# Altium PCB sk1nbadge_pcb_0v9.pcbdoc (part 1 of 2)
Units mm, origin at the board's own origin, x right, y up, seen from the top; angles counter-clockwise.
Board outline 99 x 74 mm, 4 copper layers (Top Layer, GND Plane, 3V Plane, Bottom Layer); 199 components, 158 nets, 800 pads, 392 vias.
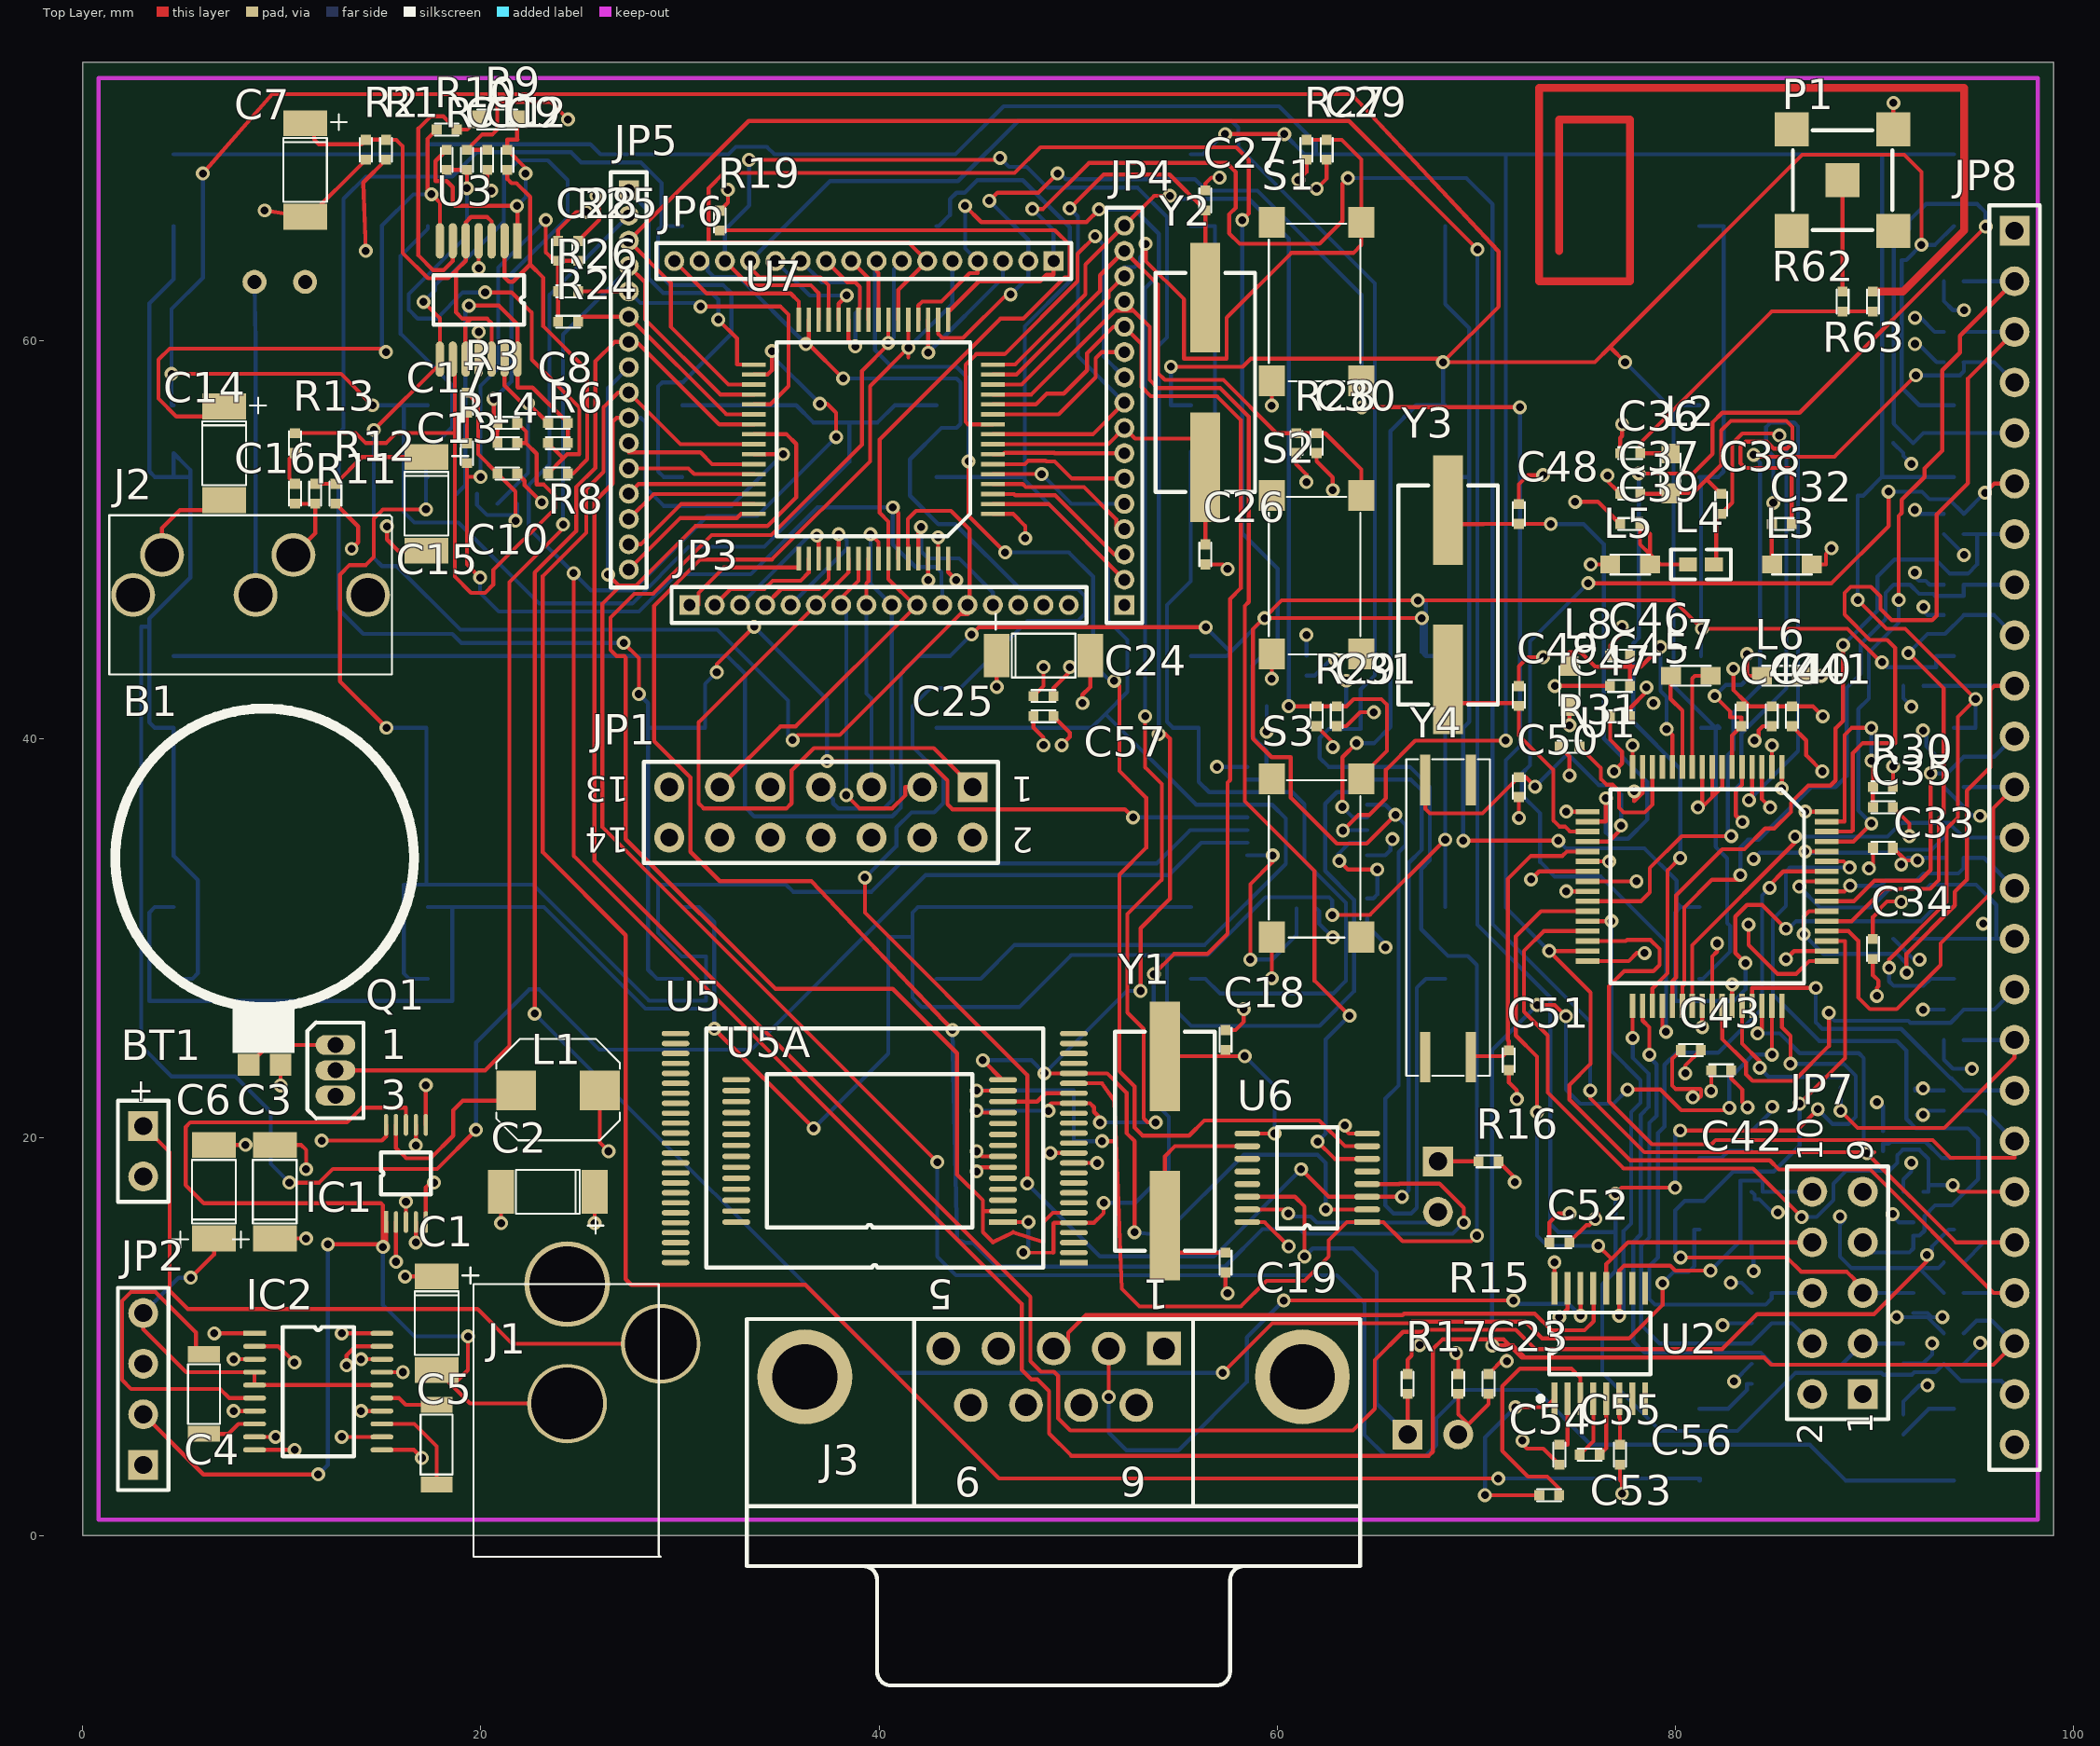
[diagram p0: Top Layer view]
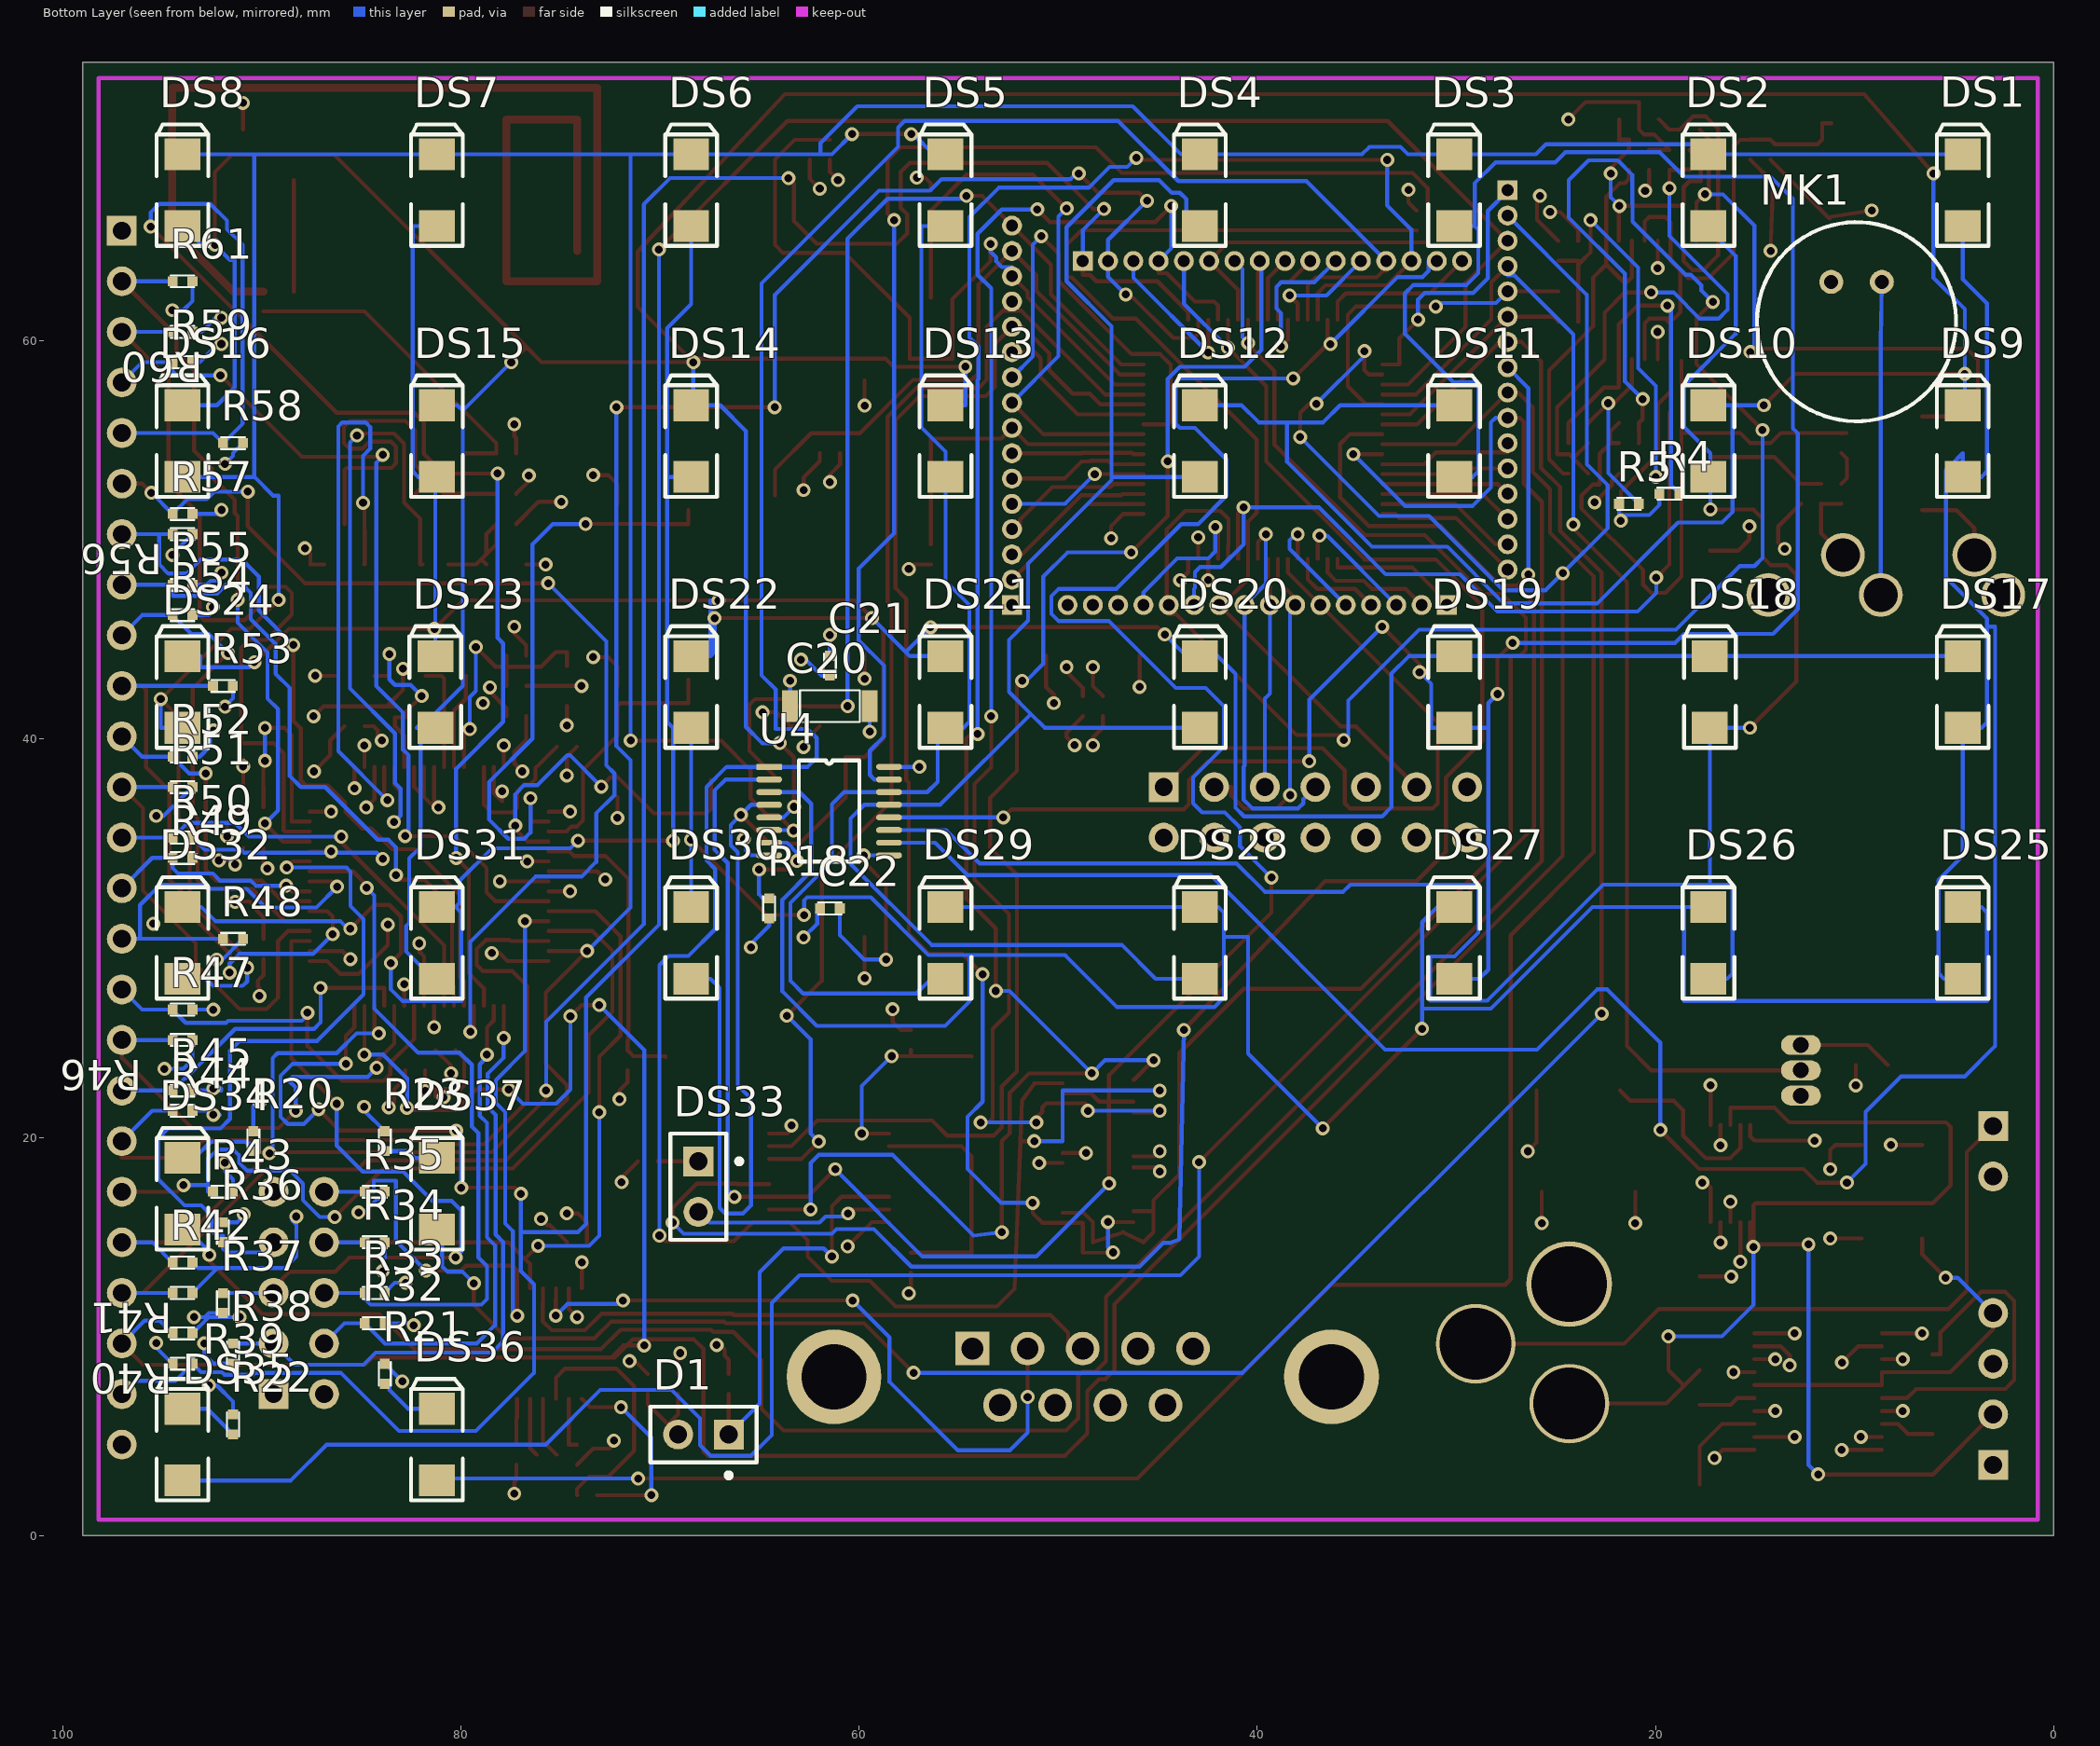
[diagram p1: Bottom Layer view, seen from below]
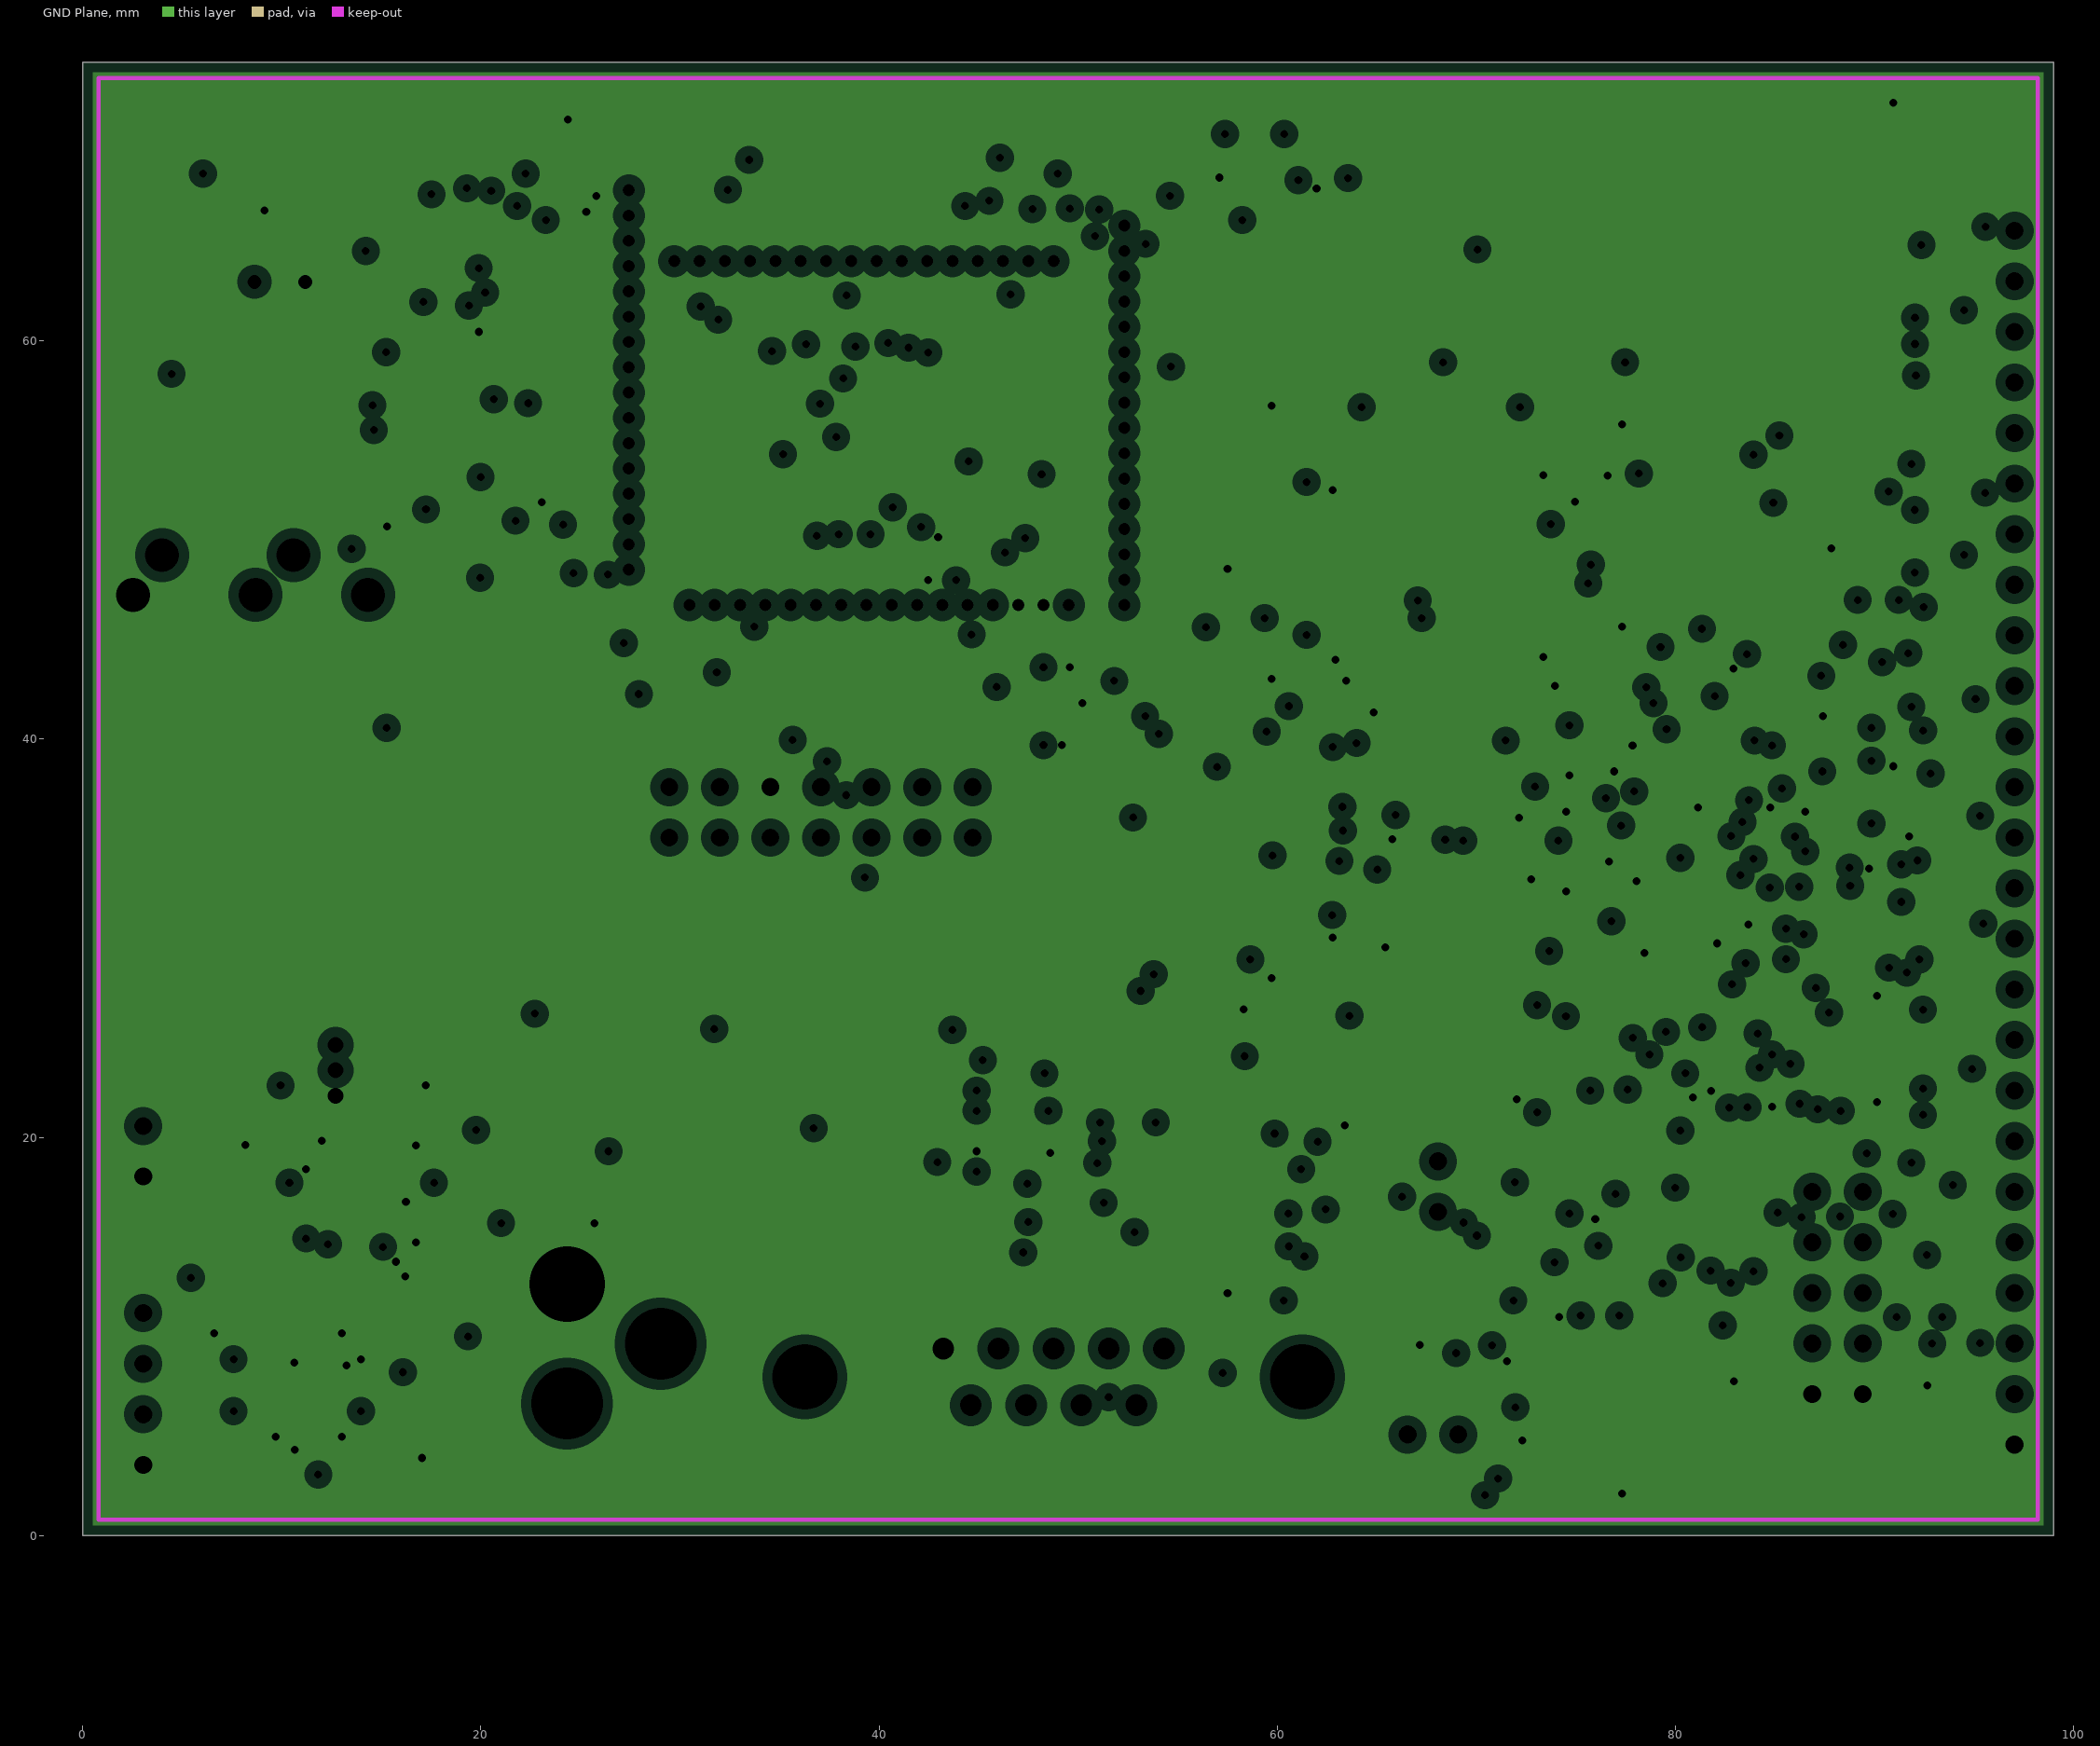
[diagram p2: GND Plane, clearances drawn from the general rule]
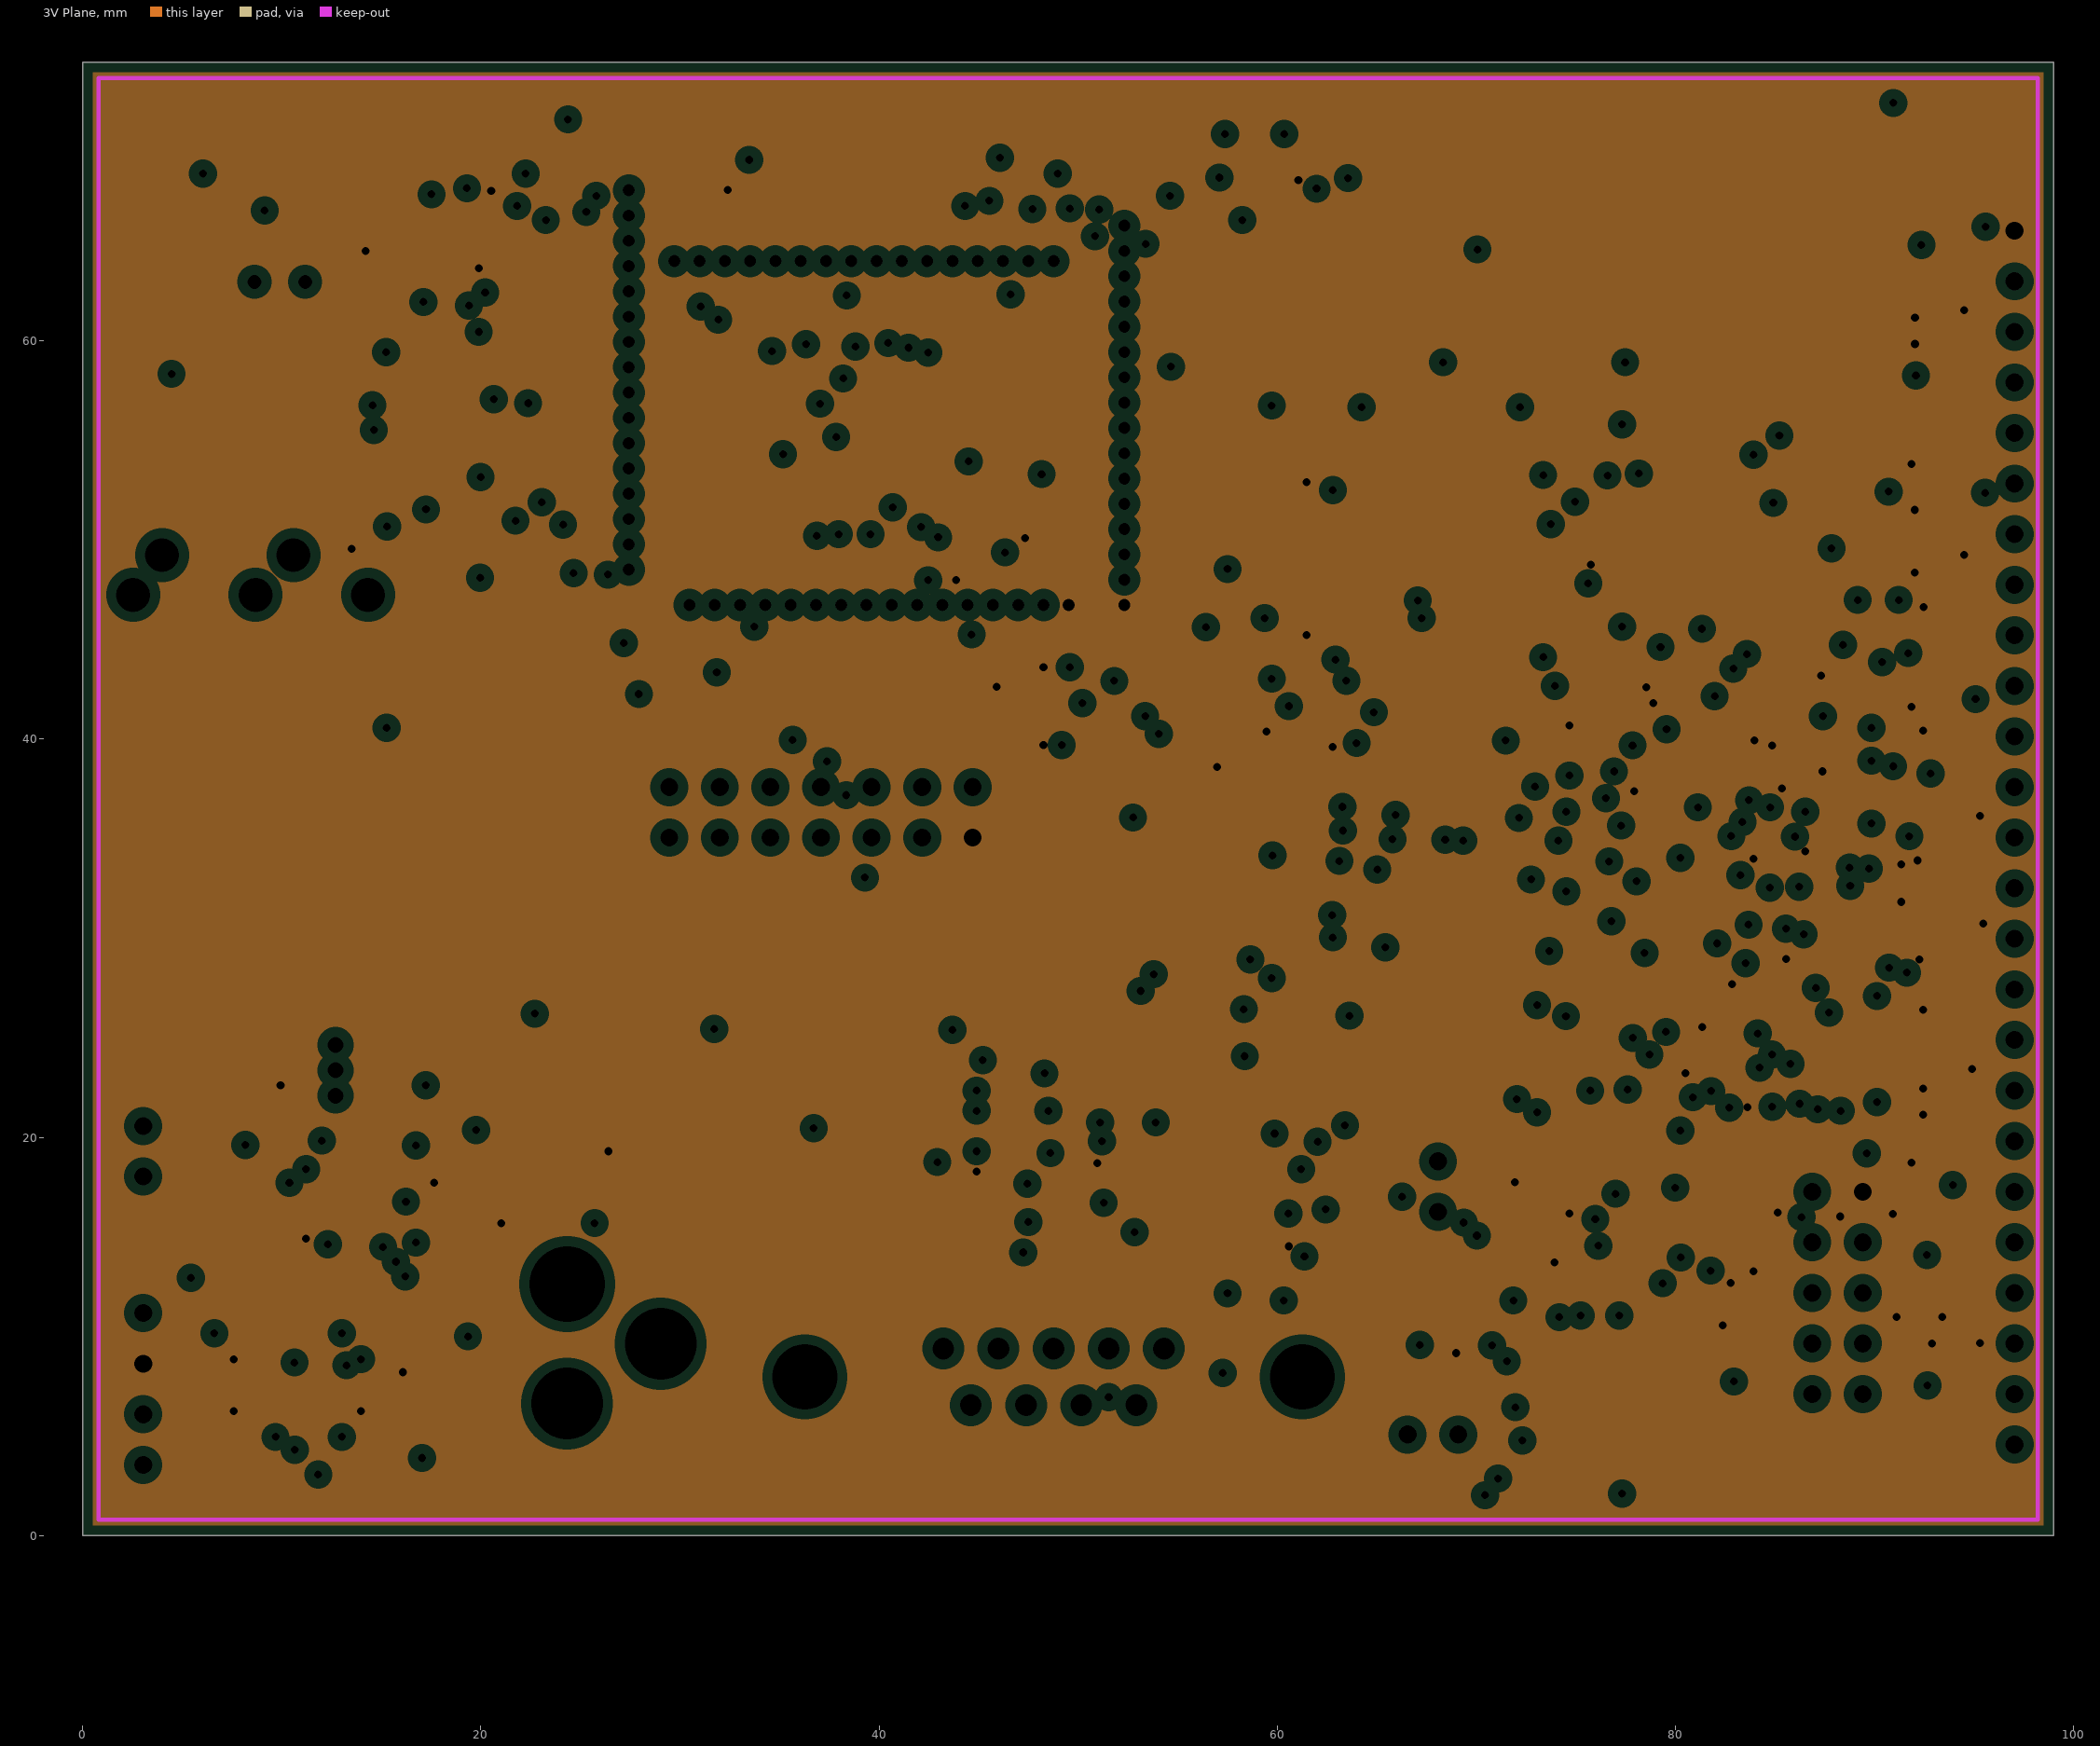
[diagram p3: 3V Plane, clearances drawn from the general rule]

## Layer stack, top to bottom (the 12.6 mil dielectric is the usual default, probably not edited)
Top Layer: signal copper 0.0356
Dielectric: core 0.32, FR-4, Dk 4.8
GND Plane: plane copper 0.0356, net GND
Dielectric: prepreg 0.32, FR-4, Dk 4.8
3V Plane: plane copper 0.0356, net 3.3V
Dielectric: core 0.32, FR-4, Dk 4.8
Bottom Layer: signal copper 0.0356

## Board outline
0,0 99,0 99,74 0,74

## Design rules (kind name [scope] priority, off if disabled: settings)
Clearance [All] p1: gap=0.2
ComponentClearance [All] p1: gap=0.254 collisioncheckmode=0
PlaneClearance [All] p1: clearance=0.508
PlaneConnect [All] p1: planeconnectstyle=Relief reliefexpansion=0.508 reliefentries=4 reliefconductorwidth=0.254 reliefairgap=0.254
PolygonConnect [All] p1: connectstyle=Relief reliefconductorwidth=0.254 reliefentries=4 polygonreliefangle="90 Angle"
RoomDefinition sk1nbadge_0v9_rf_connectors [InComponentClass('sk1nbadge_0v9_rf_connectors')] p1: confinementstyle=ConfineIn formatcopy=TRUE outline -50.8,-76.2 0,-76.2 0,-50.8 -50.8,-50.8
RoomDefinition sk1nbadge_0v9_rf [InComponentClass('sk1nbadge_0v9_rf')] p2: confinementstyle=ConfineIn formatcopy=TRUE outline -50.8,-76.2 0,-76.2 0,-50.8 -50.8,-50.8
RoomDefinition sk1nbadge_0v9_power [InComponentClass('sk1nbadge_0v9_power')] p3: confinementstyle=ConfineIn formatcopy=TRUE outline -50.8,-76.2 0,-76.2 0,-50.8 -50.8,-50.8
RoomDefinition sk1nbadge_0v9_display_mem [InComponentClass('sk1nbadge_0v9_display_mem')] p4: confinementstyle=ConfineIn formatcopy=TRUE outline -50.8,-76.2 0,-76.2 0,-50.8 -50.8,-50.8
RoomDefinition sk1badge_0v9_main [InComponentClass('sk1badge_0v9_main')] p5: confinementstyle=ConfineIn formatcopy=TRUE outline -50.8,-76.2 0,-76.2 0,-50.8 -50.8,-50.8
RoutingLayers [All] p1: top layer=Horizontal bottom layer=Vertical
RoutingVias [All] p1: holewidth=0.4 width=0.7 viastyle="Through Hole" minholewidth=0.4 minwidth=0.7 maxholewidth=0.4 maxwidth=0.7
SolderMaskExpansion [All] p1: expansion=0.102
TestPointUsage [All] p1: valid=0 allowmultiple=FALSE
Testpoint [All] p1: side=15 testpointundercomponent=TRUE minsize=1.016 maxsize=2.54 preferedsize=1.524 minholesize=0 maxholesize=1.016 preferedholesize=0.813 testpointgrid=0.025 style=1023 order=-539222988
Width [All] p1: maxlimit=0.2 minlimit=0.2 preferedwidth=0.2
14 further rules are at their usual default settings.

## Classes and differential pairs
component class sk1nbadge_0v9_rf: C32 C33 C34 C35 C36 C37 C38 C39 C40 C41 C42 C43 C44 C45 C46 C47 C48 C49 C50 C51 L2 L3 L4 L5 L6 L7 L8 P1 R30 R31 R62 R63 U1 Y3 Y4
component class sk1nbadge_0v9_rf_connectors: C52 C53 C54 C55 C56 J3 JP7 JP8 R32 R33 R34 R35 R36 R37 R38 R39 R40 R41 R42 R43 R44 R45 R46 R47 R48 R49 R50 R51 R52 R53 R54 R55 R56 R57 R58 R59 R60 R61 U2
component class sk1nbadge_0v9_power: B1 BT1 C1 C2 C3 C4 C5 C6 C7 C8 C9 C10 C11 C12 C13 C14 C15 C16 C17 IC1 IC2 J1 J2 L1 MK1 Q1 R1 R2 R3 R4 R5 R6 R7 R8 R9 R10 R11 R12 R13 R14 U3
component class sk1nbadge_0v9_display_mem: C18 C19 C20 C21 C22 C23 D1 DS1 DS2 DS3 DS4 DS5 DS6 DS7 DS8 DS9 DS10 DS11 DS12 DS13 DS14 DS15 DS16 DS17 DS18 DS19 DS20 DS21 DS22 DS23 DS24 DS25 DS26 DS27 DS28 DS29 DS30 DS31 DS32 DS33 R15 R16 R17 R18 U4 U5 U6 Y1
component class sk1badge_0v9_main: C24 C25 C26 C27 C28 C29 C30 C31 C57 DS34 DS35 DS36 DS37 JP1 JP2 JP3 JP4 JP5 JP6 R19 R20 R21 R22 R23 R24 R25 R26 R27 R28 R29 S1 S2 S3 U7 Y2

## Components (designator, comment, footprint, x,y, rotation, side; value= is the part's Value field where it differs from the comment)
B1 "Pancake Motor" PANCAKE_MOTOR 9.144,34.036 r270 top
BT1 "Batteries" BAT-2 3.048,19.304 r270 top
C1 "Cap" 6032-28 17.78,10.668 r270 top
C2 "Cap" 6032-28 23.368,17.272 r180 top
C3 "Cap Pol3" 6032-28 9.652,17.272 r90 top
C4 "" 1206 6.096,7.112 r270 top
C5 "Cap" 1206 17.78,4.572 r90 top
C6 "Cap Pol3" 6032-28 6.604,17.272 r90 top
C7 "Cap Pol3" 6032-28 11.176,68.58 r270 top
C8 "Cap" 0402 23.876,55.88 r0 top
C9 "Cap" 0402 21.336,69.088 r90 top
C10 "Cap" 0402 21.336,53.34 r180 top
C11 "Cap" 0402 19.304,69.088 r270 top
C12 "Cap" 0402 20.32,69.088 r90 top
C13 "Cap" 0402 19.304,54.356 r90 top
C14 "Cap Pol3" 6032-28 7.112,54.356 r270 top
C15 "Cap Pol3" 6032-28 17.272,51.816 r270 top
C16 "Cap" 0402 10.668,52.324 r270 top
C17 "Cap" 0402 21.336,55.88 r0 top
C18 "Cap" 0402 57.404,24.892 r270 top
C19 "Cap" 0402 57.404,13.716 r90 top
C20 "Cap" 1206 61.468,41.656 r180 bottom
C21 "Cap" 0402 61.468,43.688 r90 bottom
C22 "Cap" 0402 61.468,31.496 r180 bottom
C23 "Cap" 0402 70.612,7.62 r270 top
C24 "Cap Pol3" 6032-28 48.26,44.196 r0 top
C25 "Cap" 0402 48.26,42.164 r0 top
C26 "Cap" 0402 56.388,49.276 r90 top
C27 "Cap" 0402 56.388,67.056 r270 top
C28 "Cap" 0402 23.876,64.516 r270 top
C29 "Cap" 0402 62.484,69.596 r90 top
C30 "Cap" 0402 61.976,54.864 r90 top
C31 "Cap" 0402 62.992,41.148 r90 top
C32 "Cap" 0402 85.344,50.8 r180 top
C33 "Cap" 0402 90.424,34.544 r0 top
C34 "Cap" 0402 89.916,29.464 r90 top
C35 "Cap" 0402 90.424,36.576 r180 top
C36 "Cap" 0402 77.724,54.356 r0 top
C37 "Cap" 0402 77.724,52.324 r0 top
C38 "Cap" 0402 82.296,51.816 r270 top
C39 "Cap" 0402 77.724,50.8 r0 top
C40 "Cap" 0402 84.836,41.148 r270 top
C41 "Cap" 0402 85.852,41.148 r270 top
C42 "Cap" 0402 82.296,23.368 r0 top
C43 "Cap" 0402 80.772,24.384 r0 top
C44 "Cap" 0402 83.312,41.148 r270 top
C45 "Cap" 0402 77.216,42.672 r0 top
C46 "Cap" 0402 77.216,44.196 r0 top
C47 "Cap" 0402 77.216,41.148 r0 top
C48 "Cap" 0402 72.136,51.308 r90 top
C49 "Cap" 0402 72.136,42.164 r270 top
C50 "Cap" 0402 72.136,37.592 r90 top
C51 "Cap" 0402 71.628,23.876 r90 top
C52 "Cap" 0402 74.168,14.732 r180 top
C53 "Cap" 0402 73.66,2.032 r180 top
C54 "Cap" 0402 74.168,4.064 r90 top
C55 "Cap" 0402 75.692,4.064 r180 top
C56 "Cap" 0402 77.216,4.064 r90 top
C57 "Cap" 0402 48.26,41.148 r0 top
D1 "Photodiode" PIN2 66.548,5.08 r0 bottom
DS1 "LED" LED-1206 4.572,67.564 r90 bottom
DS2 "LED" LED-1206 17.345,67.564 r90 bottom
DS3 "LED" LED-1206 30.117,67.564 r90 bottom
DS4 "LED" LED-1206 42.89,67.564 r90 bottom
DS5 "LED" LED-1206 55.662,67.564 r90 bottom
DS6 "LED" LED-1206 68.435,67.564 r90 bottom
DS7 "LED" LED-1206 81.207,67.564 r90 bottom
DS8 "LED" LED-1206 93.98,67.564 r90 bottom
DS9 "LED" LED-1206 4.572,54.966 r90 bottom
DS10 "LED" LED-1206 17.345,54.966 r90 bottom
DS11 "LED" LED-1206 30.117,54.966 r90 bottom
DS12 "LED" LED-1206 42.89,54.966 r90 bottom
DS13 "LED" LED-1206 55.662,54.966 r90 bottom
DS14 "LED" LED-1206 68.435,54.966 r90 bottom
DS15 "LED" LED-1206 81.207,54.966 r90 bottom
DS16 "LED" LED-1206 93.98,54.966 r90 bottom
DS17 "LED" LED-1206 4.572,42.367 r90 bottom
DS18 "LED" LED-1206 17.272,42.367 r90 bottom
DS19 "LED" LED-1206 30.117,42.367 r90 bottom
DS20 "LED" LED-1206 42.89,42.367 r90 bottom
DS21 "LED" LED-1206 55.662,42.367 r90 bottom
DS22 "LED" LED-1206 68.435,42.367 r90 bottom
DS23 "LED" LED-1206 81.28,42.367 r90 bottom
DS24 "LED" LED-1206 93.98,42.367 r90 bottom
DS25 "LED" LED-1206 4.572,29.769 r90 bottom
DS26 "LED" LED-1206 17.345,29.769 r90 bottom
DS27 "LED" LED-1206 30.117,29.769 r90 bottom
DS28 "LED" LED-1206 42.89,29.769 r90 bottom
DS29 "LED" LED-1206 55.662,29.769 r90 bottom
DS30 "LED" LED-1206 68.435,29.769 r90 bottom
DS31 "LED" LED-1206 81.207,29.769 r90 bottom
DS32 "LED" LED-1206 93.98,29.769 r90 bottom
DS33 "IR LED" PIN2 68.072,18.796 r270 bottom
DS34 "LED2" LED-1206 93.98,17.17 r90 bottom
DS35 "LED2" LED-1206 93.98,4.572 r90 bottom
DS36 "LED2" LED-1206 81.207,4.572 r90 bottom
DS37 "LED2" LED-1206 81.207,17.17 r90 bottom
IC1 "TPS62056" MSOP10 15.24,15.748 r90 top
IC2 "TPS60110" TSOP/PWP/20 8.636,10.16 r0 top
J1 "Power Jack 4-10VDC" PJ-002A 21.336,8.636 r180 top
J2 "MIC and SPEAKER" SJ-3535N 2.54,47.244 r90 top
J3 "D Connector 9" DSUB1.385-2H9 48.768,-1.524 r180 top
JP1 "JTAG/ISP" HDR2X7 44.704,37.592 r180 top
JP2 "Power" HDR1X4 3.048,3.556 r90 top
JP3 "MHDR1X16" MHDR1X16 30.48,46.736 r0 top
JP4 "MHDR1X16" MHDR1X16 52.324,46.736 r90 top
JP5 "MHDR1X16" MHDR1X16 27.432,67.564 r270 top
JP6 "MHDR1X16" MHDR1X16 48.768,64.008 r180 top
JP7 "ISP/DB" HDR2X5 89.408,7.112 r90 top
JP8 "Header 25" HDR1X25 97.028,65.532 r270 top
L1 "Inductor" DN4835 23.876,22.352 r0 top
L2 "Inductor" 0603 79.756,53.34 r90 top
L3 "Inductor" 0603 85.852,48.768 r180 top
L4 "Inductor" C1005-0402 81.28,48.768 r0 top
L5 "Filter Bead" 0603 77.724,48.768 r0 top
L6 "Filter Bead" 0603 85.344,43.18 r180 top
L7 "Inductor" 0603 80.772,43.18 r0 top
L8 "Filter Bead" 0603 74.676,42.672 r90 top
MK1 "Mic2" MIC54B 11.176,60.96 r180 bottom
P1 "SMA" SMA/SM 88.392,68.072 r0 top
Q1 "NFET ZVNL110A" BCY-W3/H.8 12.7,23.368 r0 top
R1 "Res1" 0402 15.24,69.596 r270 top
R2 "Res1" 0402 14.224,69.596 r90 top
R3 "Res1" 0402 19.304,56.896 r90 top
R4 "Res1" 0402 19.304,52.324 r180 bottom
R5 "Res1" 0402 21.336,51.816 r180 bottom
R6 "Res1" 0402 23.876,54.864 r180 top
R7 "Res1" 0402 18.288,69.088 r90 top
R8 "Res1" 0402 23.876,53.34 r0 top
R9 "Res1" 0603 20.828,71.12 r180 top
R10 "Res1" 0402 18.288,70.612 r180 top
R11 "Res1" 0402 11.684,52.324 r90 top
R12 "Res1" 0402 12.7,52.324 r90 top
R13 "Res1" 0402 10.668,54.864 r270 top
R14 "Res1" 0402 21.336,54.864 r0 top
R15 "Res1" 0402 69.088,7.62 r90 top
R16 "Res1" 0402 70.612,18.796 r0 top
R17 "Res1" 0402 66.548,7.62 r270 top
R18 "Res1" 0402 64.516,31.496 r90 bottom
R19 "Res1" 0402 32.004,66.04 r90 top
R20 "Res1" 0402 90.424,19.812 r90 bottom
R21 "Res1" 0402 83.82,8.128 r90 bottom
R22 "Res1" 0402 91.44,5.588 r90 bottom
R23 "Res1" 0402 83.82,19.812 r90 bottom
R24 "Res1" 0402 24.384,60.96 r180 top
R25 "Res1" 0402 24.892,64.516 r270 top
R26 "Res1" 0402 24.384,62.484 r180 top
R27 "Res1" 0402 61.468,69.596 r270 top
R28 "Res1" 0402 60.96,54.864 r270 top
R29 "Res1" 0402 61.976,41.148 r270 top
R30 "Res1" 0402 90.424,37.592 r180 top
R31 "Res1" 0402 74.676,39.624 r0 top
R32 "Res1" 0402 84.328,10.668 r180 bottom
R33 "Res1" 0402 84.328,12.192 r180 bottom
R34 "Res1" 0402 84.328,14.732 r180 bottom
R35 "Res1" 0402 84.328,17.272 r180 bottom
R36 "Res1" 0402 91.948,15.24 r90 bottom
R37 "Res1" 0402 91.948,11.684 r270 bottom
R38 "Res1" 0402 91.44,9.144 r270 bottom
R39 "Res1" 0402 93.98,8.636 r0 bottom
R40 "Res1" 0402 93.98,10.16 r180 bottom
R41 "Res1" 0402 93.98,12.192 r180 bottom
R42 "Res1" 0402 93.98,13.716 r180 bottom
R43 "Res1" 0402 91.948,17.272 r180 bottom
R44 "Res1" 0402 93.98,21.336 r180 bottom
R45 "Res1" 0402 93.98,22.352 r180 bottom
R46 "Res1" 0402 93.98,24.892 r180 bottom
R47 "Res1" 0402 93.98,26.416 r180 bottom
R48 "Res1" 0402 91.44,29.972 r180 bottom
R49 "Res1" 0402 93.98,34.036 r180 bottom
R50 "Res1" 0402 93.98,35.052 r180 bottom
R51 "Res1" 0402 93.98,37.592 r180 bottom
R52 "Res1" 0402 93.98,39.116 r180 bottom
R53 "Res1" 0402 91.948,42.672 r180 bottom
R54 "Res1" 0402 93.98,46.228 r180 bottom
R55 "Res1" 0402 93.98,47.752 r180 bottom
R56 "Res1" 0402 93.98,50.292 r180 bottom
R57 "Res1" 0402 93.98,51.308 r180 bottom
R58 "Res1" 0402 91.44,54.864 r180 bottom
R59 "Res1" 0402 93.98,58.928 r180 bottom
R60 "Res1" 0402 93.98,60.452 r180 bottom
R61 "Res1" 0402 93.98,62.992 r180 bottom
R62 "Res1" 0402 88.392,61.976 r90 top
R63 "Res1" 0402 89.916,61.976 r90 top
S1 "SW-PB" B3S-1000 61.976,61.976 r90 top
S2 "SW-PB" B3S-1000 61.976,48.26 r90 top
S3 "SW-PB" B3S-1000 61.976,34.036 r90 top
U1 "CC1010" TQFP64 85.344,38.608 r270 top
U2 "MAX3232CUE" TSSO5x6-G16 76.2,9.652 r0 top
U3 "LMV324" TSSOP14 21.844,65.024 r270 top
U4 "MAX6950" QSOP16 64.516,38.608 r180 bottom
U5 "ATMEL DATAFLASH" TSSOP48/DF 49.784,13.716 r180 top
U5A "Comment" TSSOP28/DF 46.228,15.748 r180 top
U6 "MAX3100" QSOP16 64.516,15.748 r180 top
U7 "MSP430F149" QFP64 45.72,51.308 r180 top
Y1 "3.6864 MHz" HCM49 54.356,19.812 r270 top
Y2 "8MHz" HCM49 56.388,57.912 r270 top
Y3 "14.7456 MHz" HCM49 68.58,47.244 r270 top
Y4 "32.768 kHz" MC-405 68.58,30.988 r270 top

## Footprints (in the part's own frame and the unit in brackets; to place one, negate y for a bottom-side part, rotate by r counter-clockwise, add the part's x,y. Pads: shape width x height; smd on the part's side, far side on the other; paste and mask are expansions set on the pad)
0402 [mm]
  rect 0.5x0.5 smd: 1(-0.5,0) 2(0.5,0)
  silkscreen extent -0.6,-0.3 0.6,0.3
0603 [mm]
  rect 1x0.9 smd: 1(-1,0) 2(1,0)
  silkscreen extent -1,-0.5 1,0.5
1206 [mm]
  rect 0.8x1.6 smd: 1(-2,0) 2(2,0)
  silkscreen extent -1.5,-0.8 1.5,0.8
6032-28 [mm]
  rect 1.3x2.2 smd: 1(-2.35,0) 2(2.35,0)
  silkscreen extent -2.8,-1.1 1.6,2.1
B3S-1000 [mm]
  rect 1.55x1.3 smd: 1(-3.975,2.25) 1(3.975,2.25) 2(-3.975,-2.25) 2(3.975,-2.25)
  silkscreen extent -4,-2.2 3.9,2.4
BAT-2 [mm]
  rect 1.5x1.5 hole 0.9: 1(-1.27,0)
  round 1.5 hole 0.9: 2(1.27,0)
  silkscreen extent -2.54,-1.27 2.54,1.27
BCY-W3/H.8 [mm]
  oval 2x1 hole 0.8: 1(0,1.27) 2(0,0) 3(0,-1.27)
  silkscreen extent -1.41,-2.41 1.41,2.41
C1005-0402 [mm]
  rect 0.9x0.7 smd: 1(-0.65,0) 2(0.65,0)
  silkscreen extent -1.5,-0.75 1.5,0.75
DN4835 [mm]
  rect 2x2 smd: 1(-2.1,0) 2(2.1,0)
  silkscreen extent -3.1,-2.5 3.1,2.6
DSUB1.385-2H9 [mm]
  rect 1.69x1.69 hole 1.09: 1(-5.54,-10.92)
  round 1.69 hole 1.09: 2(-2.77,-10.92) 3(0,-10.92) 4(2.77,-10.92) 5(5.54,-10.92) 6(-4.155,-8.08) 7(-1.385,-8.08) 8(1.385,-8.08) 9(4.155,-8.08)
  round 4.76 hole 3.26: 10(-12.495,-9.5) 11(12.495,-9.5)
  silkscreen extent -15.4,-12.4 15.4,6
HCM49 [mm]
  rect 5.5x1.5 smd: 1(-4.25,0) 2(4.25,0)
  silkscreen extent -5.5,-2.5 5.5,2.5
HDR1X4 [mm]
  rect 1.5x1.5 hole 0.9: 1(0,0)
  round 1.5 hole 0.9: 2(2.54,0) 3(5.08,0) 4(7.62,0)
  silkscreen extent -1.27,-1.27 8.89,1.27
HDR1X25 [mm]
  rect 1.5x1.5 hole 0.9: 1(0,0)
  round 1.5 hole 0.9: 2(2.54,0) 3(5.08,0) 4(7.62,0) 5(10.16,0) 6(12.7,0) 7(15.24,0) 8(17.78,0) 9(20.32,0) 10(22.86,0) 11(25.4,0) 12(27.94,0) 13(30.48,0) 14(33.02,0) 15(35.56,0) 16(38.1,0) 17(40.64,0) 18(43.18,0) 19(45.72,0) 20(48.26,0) 21(50.8,0) 22(53.34,0) 23(55.88,0) 24(58.42,0) 25(60.96,0)
  silkscreen extent -1.27,-1.27 62.23,1.27
HDR2X5 [mm]
  rect 1.5x1.5 hole 0.9: 1(0,0)
  round 1.5 hole 0.9: 2(0,2.54) 3(2.54,0) 4(2.54,2.54) 5(5.08,0) 6(5.08,2.54) 7(7.62,0) 8(7.62,2.54) 9(10.16,0) 10(10.16,2.54)
  silkscreen extent -1.27,-1.27 11.43,3.81
HDR2X7 [mm]
  rect 1.5x1.5 hole 0.9: 1(0,0)
  round 1.5 hole 0.9: 2(0,2.54) 3(2.54,0) 4(2.54,2.54) 5(5.08,0) 6(5.08,2.54) 7(7.62,0) 8(7.62,2.54) 9(10.16,0) 10(10.16,2.54) 11(12.7,0) 12(12.7,2.54) 13(15.24,0) 14(15.24,2.54)
  silkscreen extent -1.27,-1.27 16.51,3.81
LED-1206 [mm]
  rect 1.6x1.8 smd: 1(-1.8,0) 2(1.8,0)
  silkscreen extent -2.8,-1.3 3.3,1.3
MC-405 [mm]
  rect 2.54x0.51 smd: 1(-6.957,-1.145) 1(-6.957,1.145) 2(6.957,-1.145) 2(6.957,1.145)
  silkscreen extent -8,-2.1 7.9,2.1
MHDR1X16 [mm]
  rect 1x1 hole 0.6: 1(0,0)
  round 1 hole 0.6: 2(1.27,0) 3(2.54,0) 4(3.81,0) 5(5.08,0) 6(6.35,0) 7(7.62,0) 8(8.89,0) 9(10.16,0) 10(11.43,0) 11(12.7,0) 12(13.97,0) 13(15.24,0) 14(16.51,0) 15(17.78,0) 16(19.05,0)
  silkscreen extent -0.9,-0.9 19.95,0.9
MIC54B [mm]
  round 1.2 hole 0.7: 1(0,2) 2(2.54,2)
  silkscreen extent -3.73,-5 6.27,5
MSOP10 [mm]
  rect 1.1x0.22 smd: 1(0,0)
  oval 1.1x0.22 smd: 2(0,-0.5) 3(0,-1) 4(0,-1.5) 5(0,-2) 6(4.88,-2) 7(4.88,-1.5) 8(4.88,-1) 9(4.88,-0.5) 10(4.88,0)
  silkscreen extent 1.39,-2.25 3.49,0.25
PANCAKE_MOTOR [mm]
  rect 1.1x1.1 smd: 1(10.4,0.8) 2(10.4,-0.8)
  silkscreen extent -7.5,-7.5 9.8,7.5
PIN2 [mm]
  rect 1.5x1.5 hole 0.9: 1(0,0)
  round 1.5 hole 0.9: 2(2.54,0)
  silkscreen extent -1.4,-1.4 3.94,2.17
PJ-002A [mm]
  round 4 hole 3.6: 1(-3,2) 2(-7.7,-1)
  round 4.3 hole 3.8: 3(-3,-4)
  silkscreen extent -7.7,-4 1.7,9.7
QFP64 [mm]
  rect 1.2x0.22 smd: 1(0,0) 2(0,-0.5) 3(0,-1) 4(0,-1.5) 5(0,-2) 6(0,-2.5) 7(0,-3) 8(0,-3.5) 9(0,-4) 10(0,-4.5) 11(0,-5) 12(0,-5.5) 13(0,-6) 14(0,-6.5) 15(0,-7) 16(0,-7.5) 33(12,-7.5) 34(12,-7) 35(12,-6.5) 36(12,-6) 37(12,-5.5) 38(12,-5) 39(12,-4.5) 40(12,-4) 41(12,-3.5) 42(12,-3) 43(12,-2.5) 44(12,-2) 45(12,-1.5) 46(12,-1) 47(12,-0.5) 48(12,0)
  rect 0.22x1.2 smd: 17(2.25,-9.75) 18(2.75,-9.75) 19(3.25,-9.75) 20(3.75,-9.75) 21(4.25,-9.75) 22(4.75,-9.75) 23(5.25,-9.75) 24(5.75,-9.75) 25(6.25,-9.75) 26(6.75,-9.75) 27(7.25,-9.75) 28(7.75,-9.75) 29(8.25,-9.75) 30(8.75,-9.75) 31(9.25,-9.75) 32(9.75,-9.75) 49(9.75,2.25) 50(9.25,2.25) 51(8.75,2.25) 52(8.25,2.25) 53(7.75,2.25) 54(7.25,2.25) 55(6.75,2.25) 56(6.25,2.25) 57(5.75,2.25) 58(5.25,2.25) 59(4.75,2.25) 60(4.25,2.25) 61(3.75,2.25) 62(3.25,2.25) 63(2.75,2.25) 64(2.25,2.25)
  silkscreen extent 1.13,-8.61 10.87,1.12
QSOP16 [mm]
  rect 1.3x0.3 smd: 1(0,0)
  oval 1.3x0.3 smd: 2(0,-0.635) 3(0,-1.27) 4(0,-1.905) 5(0,-2.54) 6(0,-3.175) 7(0,-3.81) 8(0,-4.445) 9(6.02,-4.445) 10(6.02,-3.81) 11(6.02,-3.175) 12(6.02,-2.54) 13(6.02,-1.905) 14(6.02,-1.27) 15(6.02,-0.635) 16(6.02,0)
  silkscreen extent 1.48,-4.76 4.54,0.32
SJ-3535N [mm]
  round 2.2 hole 1.7: 1(2,-8.05) 2(0,-6.15) 3(0,-11.8) 4(2,-1.45) 5(0,0)
  silkscreen extent -4,-13 4,1.2
SMA/SM [mm]
  rect 1.7x1.7 smd: 1(0,0) 2(-2.55,-2.55) 2(-2.55,2.55) 2(2.55,-2.55) 2(2.55,2.55)
  silkscreen extent -2.5,-2.5 2.5,2.5
TQFP64 [mm]
  rect 1.2x0.27 smd: 1(0,0) 2(0,-0.5) 3(0,-1) 4(0,-1.5) 5(0,-2) 6(0,-2.5) 7(0,-3) 8(0,-3.5) 9(0,-4) 10(0,-4.5) 11(0,-5) 12(0,-5.5) 13(0,-6) 14(0,-6.5) 15(0,-7) 16(0,-7.5) 33(12,-7.5) 34(12,-7) 35(12,-6.5) 36(12,-6) 37(12,-5.5) 38(12,-5) 39(12,-4.5) 40(12,-4) 41(12,-3.5) 42(12,-3) 43(12,-2.5) 44(12,-2) 45(12,-1.5) 46(12,-1) 47(12,-0.5) 48(12,0)
  rect 0.27x1.2 smd: 17(2.25,-9.75) 18(2.75,-9.75) 19(3.25,-9.75) 20(3.75,-9.75) 21(4.25,-9.75) 22(4.75,-9.75) 23(5.25,-9.75) 24(5.75,-9.75) 25(6.25,-9.75) 26(6.75,-9.75) 27(7.25,-9.75) 28(7.75,-9.75) 29(8.25,-9.75) 30(8.75,-9.75) 31(9.25,-9.75) 32(9.75,-9.75) 49(9.75,2.25) 50(9.25,2.25) 51(8.75,2.25) 52(8.25,2.25) 53(7.75,2.25) 54(7.25,2.25) 55(6.75,2.25) 56(6.25,2.25) 57(5.75,2.25) 58(5.25,2.25) 59(4.75,2.25) 60(4.25,2.25) 61(3.75,2.25) 62(3.25,2.25) 63(2.75,2.25) 64(2.25,2.25)
  silkscreen extent 1.13,-8.61 10.87,1.12
TSOP/PWP/20 [mm]
  rect 1.15x0.25 smd: 1(0,0)
  oval 1.15x0.25 smd: 2(0,-0.65) 3(0,-1.3) 4(0,-1.95) 5(0,-2.6) 6(0,-3.25) 7(0,-3.9) 8(0,-4.55) 9(0,-5.2) 10(0,-5.85) 11(6.4,-5.85) 12(6.4,-5.2) 13(6.4,-4.55) 14(6.4,-3.9) 15(6.4,-3.25) 16(6.4,-2.6) 17(6.4,-1.95) 18(6.4,-1.3) 19(6.4,-0.65) 20(6.4,0)
  silkscreen extent 1.41,-6.17 4.99,0.33
TSSO5x6-G16 [mm]
  rect 0.3x1.65 smd: 1(-2.275,-2.775) 2(-1.625,-2.775) 3(-0.975,-2.775) 4(-0.325,-2.775) 5(0.325,-2.775) 6(0.975,-2.775) 7(1.625,-2.775) 8(2.275,-2.775) 9(2.275,2.775) 10(1.625,2.775) 11(0.975,2.775) 12(0.325,2.775) 13(-0.325,2.775) 14(-0.975,2.775) 15(-1.625,2.775) 16(-2.275,2.775)
  silkscreen extent -3.1,-2.9 2.55,1.55
TSSOP14 [mm]
  rect 1.78x0.42 smd: 1(0,0)
  oval 1.78x0.42 smd: 2(0,-0.65) 3(0,-1.3) 4(0,-1.95) 5(0,-2.6) 6(0,-3.25) 7(0,-3.9) 8(5.94,-3.9) 9(5.94,-3.25) 10(5.94,-2.6) 11(5.94,-1.95) 12(5.94,-1.3) 13(5.94,-0.65) 14(5.94,0)
  silkscreen extent 1.73,-4.22 4.21,0.33
TSSOP28/DF [mm]
  rect 1.4x0.27 smd: 1(0,0)
  oval 1.4x0.27 smd: 2(0,-0.55) 3(0,-1.1) 4(0,-1.65) 5(0,-2.2) 6(0,-2.75) 7(0,-3.3) 8(0,-3.85) 9(0,-4.4) 10(0,-4.95) 11(0,-5.5) 12(0,-6.05) 13(0,-6.6) 14(0,-7.15) 15(13.4,-7.15) 16(13.4,-6.6) 17(13.4,-6.05) 18(13.4,-5.5) 19(13.4,-4.95) 20(13.4,-4.4) 21(13.4,-3.85) 22(13.4,-3.3) 23(13.4,-2.75) 24(13.4,-2.2) 25(13.4,-1.65) 26(13.4,-1.1) 27(13.4,-0.55) 28(13.4,0)
  silkscreen extent 1.53,-7.42 11.87,0.27
TSSOP48/DF [mm]
  rect 1.4x0.27 smd: 1(0,0)
  oval 1.4x0.27 smd: 2(0,-0.5) 3(0,-1) 4(0,-1.5) 5(0,-2) 6(0,-2.5) 7(0,-3) 8(0,-3.5) 9(0,-4) 10(0,-4.5) 11(0,-5) 12(0,-5.5) 13(0,-6) 14(0,-6.5) 15(0,-7) 16(0,-7.5) 17(0,-8) 18(0,-8.5) 19(0,-9) 20(0,-9.5) 21(0,-10) 22(0,-10.5) 23(0,-11) 24(0,-11.5) 25(20,-11.5) 26(20,-11) 27(20,-10.5) 28(20,-10) 29(20,-9.5) 30(20,-9) 31(20,-8.5) 32(20,-8) 33(20,-7.5) 34(20,-7) 35(20,-6.5) 36(20,-6) 37(20,-5.5) 38(20,-5) 39(20,-4.5) 40(20,-4) 41(20,-3.5) 42(20,-3) 43(20,-2.5) 44(20,-2) 45(20,-1.5) 46(20,-1) 47(20,-0.5) 48(20,0)
  silkscreen extent 1.53,-11.75 18.46,0.25

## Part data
B1: library part "Motor Servo", "Servo Motor"
BT1: library part Battery, "Multicell Battery"
C1 C2 C5 C8 C9 C10 C11 C12 C13 C16 C17 C18 C19 C20 C21 C22 C23 C25 C26 C27 C28 C29 C30 C31 C32 C33 C34 C35 C36 C37 C38 C39 C40 C41 C42 C43 C44 C45 C46 C47 C48 C49 C50 C51 C52 C53 C54 C55 C56 C57: "Capacitor"
C3 C6 C7 C14 C15 C24: "Polarized Capacitor (Surface Mount)"
C4: library part Cap, "Capacitor"
D1: library part "Photo Sen", "Photosensitive Diode"
DS1 DS2 DS3 DS4 DS5 DS6 DS7 DS8 DS9 DS10 DS11 DS12 DS13 DS14 DS15 DS16 DS17 DS18 DS19 DS20 DS21 DS22 DS23 DS24 DS25 DS26 DS27 DS28 DS29 DS30 DS31 DS32 DS33: library part LED2, "Typical RED, GREEN, YELLOW, AMBER GaAs LED"
DS34 DS35 DS36 DS37: "Typical RED, GREEN, YELLOW, AMBER GaAs LED"
IC1: "TI STEP DOWN CONVERTER"
IC2: "TI CHARGE PUMP DC/DC CONVERTER"
J1: library part Phonejack, "2-Conductor Jack with 1 break contact"
J2: library part "Phonejack Stero SW", "3-Conductor Jack with 2 break contacts (normals) and 1 auxiliary make contact"
J3: "Receptacle Assembly, 9 Position, Right Angle"
JP1: library part "Header 7X2", "Header, 7-Pin, Dual row"
JP2: library part "Header 4", "Header, 4-Pin"
JP3 JP4 JP5 JP6: "Header, 16-Pin"
JP7: library part "Header 5X2", "Header, 5-Pin, Dual row"
JP8: "Header, 25-Pin"
L5 L6 L8: library part Inductor, "Inductor"
MK1: "Microphone"
P1: "SMA Straight Connector"
Q1: library part MOSFET-N, "N-Channel MOSFET"
R1 R2 R3 R4 R5 R6 R7 R8 R9 R10 R11 R12 R13 R14 R15 R16 R17 R18 R19 R20 R21 R22 R23 R24 R25 R26 R27 R28 R29 R30 R31 R32 R33 R34 R35 R36 R37 R38 R39 R40 R41 R42 R43 R44 R45 R46 R47 R48 R49 R50 R51 R52 R53 R54 R55 R56 R57 R58 R59 R60 R61 R62 R63: "Resistor"
S1 S2 S3: "Switch"
U2: "3.0V TO 5.5V, Low-Power, up to 1Mbps, True RS-232 Transceiver Using Four 0.1µF External Capacitor"
U3: "Quad Low Voltage Op Amp"
Y1 Y2 Y3 Y4: library part XTAL, "Crystal Oscillator"

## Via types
v1: diameter 0.7, hole 0.4, Top Layer to Bottom Layer, 392 vias

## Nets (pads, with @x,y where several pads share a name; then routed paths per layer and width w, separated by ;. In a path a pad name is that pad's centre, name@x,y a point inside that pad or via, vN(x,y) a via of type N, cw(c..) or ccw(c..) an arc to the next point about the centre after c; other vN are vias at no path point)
3.3V: B1.1 C2.2 C3.1 C12.1 C20.2 C21.2 C24.1 C25.1 C33.2 C34.2 C40.2 C41.2 C42.2 C43.2 C47.2 C52.2 C57.1 IC1.5 IC2.3 IC2.7 IC2.14 IC2.17 JP1.2 JP2.3 JP3.16 JP4.1 JP7.9 JP8.1 L1.2 L5.1 L6.1 L8.1 R1.2 R12.1 R15.2 R16.2 R19.2 R27.2 R28.2 R29.2 R32.2 R33.2 R34.2 R35.2 R36.2 R37.2 R38.2 R39.2 R40.2 R41.2 R42.2 R43.2 R44.2 R45.2 R46.2 R47.2 R48.2 R49.2 R50.2 R51.2 R52.2 R53.2 R54.2 R55.2 R56.2 R57.2 R58.2 R59.2 R60.2 R61.2 U1.1 U1.2 U1.15 U1.40 U1.43 U1.50 U1.60 U2.16 U3.4 U4.16 U5.11 U5A.6 U6.16 U7.1 U7.64 | length 147.5
  Top Layer w0.2: v1(7.584,6.26) IC2.7@8.636,6.26 ; v1(7.584,8.86) IC2.3@8.636,8.86 ; C3.1@9.652,14.922 v1(11.229,14.922) ; v1(9.944,22.609) B1.1@9.944,23.636 ; R12.1@12.7,51.824 13.843,50.681 13.843,49.886 v1(13.513,49.555) ; v1(13.984,6.26) IC2.14@15.036,6.26 ; v1(14.224,64.516) 14.097,67.953 R1.2@15.24,69.096 ; IC2.17@15.036,8.21 v1(16.088,8.21) ; IC1.5@17.24,15.748 17.24,17.494 17.475,17.729 v1(17.646,17.729) ; v1(19.894,63.657) U3.4@19.894,65.024 ; C12.1@20.32,68.588 20.32,67.742 v1(20.523,67.539) ; v1(21.018,15.695) C2.2@21.018,17.272 ; L1.2@25.976,22.352 25.976,19.744 v1(26.416,19.304) ; R19.2@32.004,66.54 32.41,66.946 v1(32.41,67.586) ; U7.64@43.47,49.058 43.47,48.387 v1(43.876,47.981) ; v1(44.9,18.288) 45.11,18.498 U5A.6@46.228,18.498 ; U7.1@45.72,51.308 46.736,51.308 47.346,50.698 v1(47.346,50.089) ; v1(45.91,42.619) C24.1@45.91,44.196 ; C57.1@47.76,41.148 47.76,40.581 48.26,40.081 v1(48.26,39.696) ; C25.1@47.76,42.164 48.26,42.664 v1(48.26,43.616) ; U5.11@49.784,18.716 v1(50.961,18.716) ; U6.16@58.496,15.748 59.36,15.748 v1(60.579,14.529) ; R28.2@60.96,54.364 60.96,53.801 61.468,53.293 v1(61.468,52.912) ; v1(61.062,68.072) 61.468,68.478 R27.2@61.468,69.096 ; R29.2@61.976,40.648 62.789,39.835 v1(62.789,39.602) ; v1(68.986,9.169) 69.088,9.169 R15.2@69.088,8.12 ; R16.2@71.112,18.796 71.933,17.975 v1(71.933,17.75) ; C52.2@73.668,14.732 73.668,15.724 74.128,16.184 v1(74.676,16.184) ; U2.16@73.925,12.427 v1(73.925,13.729) ; v1(74.676,40.695) L8.1@74.676,41.672 ; v1(75.747,48.768) L5.1@76.724,48.768 ; C47.2@77.716,41.148 77.716,41.555 78.537,42.376 v1(78.537,42.6) ; v1(77.927,37.379) 77.927,36.881 78.176,37.13 78.344,37.298 78.344,37.379 U1.15@78.344,38.608 ; v1(80.493,23.216) 80.493,23.605 C43.2@81.272,24.384 ; v1(81.344,25.531) U1.40@81.344,26.608 ; C42.2@82.796,23.368 82.796,22.961 83.299,22.458 83.363,22.394 83.363,21.768 v1(83.617,21.514) ; U1.43@82.844,26.608 v1(82.844,27.685) ; v1(83.972,39.929) 84.176,40.132 84.176,40.437 84.387,40.648 C40.2@84.836,40.648 ; U1.2@84.844,38.608 v1(84.844,39.685) ; v1(85.344,37.531) U1.1@85.344,38.608 ; v1(85.547,28.952) 85.954,29.358 U1.50@87.594,29.358 ; C41.2@85.852,40.648 86.563,39.937 86.563,39.192 v1(87.376,38.379) ; L6.1@86.344,43.18 v1(87.321,43.18) ; v1(86.517,34.358) U1.60@87.594,34.358 ; C34.2@89.916,29.964 89.916,31.064 90.272,31.42 90.272,31.496 90.627,31.852 91.313,31.852 v1(91.338,31.826) ; C33.2@90.924,34.544 91.55,33.918 91.559,33.909 v1(92.151,33.909)
  Bottom Layer w0.2: v1(56.972,38.608) U4.16@58.496,38.608 ; v1(59.468,40.379) C20.2@59.468,41.656 ; C21.2@61.468,44.188 v1(61.468,45.234) ; v1(82.372,10.566) 82.474,10.668 R32.2@83.828,10.668 ; v1(82.779,12.7) 83.32,12.7 R33.2@83.828,12.192 ; R34.2@83.828,14.732 83.828,13.961 83.922,13.868 v1(83.922,13.28) ; R35.2@83.828,17.272 83.972,17.128 83.972,16.891 84.209,16.891 84.869,16.231 v1(85.141,16.231) ; v1(83.922,33.985) 84.226,34.29 86.517,34.29 90.881,34.29 91.034,34.442 92.87,34.442 R50.2@93.48,35.052 ; v1(88.265,16.027) 88.265,15.621 ; v1@88.468,15.824 88.265,15.621 ; v1(90.907,16.154) 90.907,16.053 91.219,15.74 R36.2@91.948,15.74 ; R48.2@90.94,29.972 91.981,28.931 v1(92.253,28.931) ; R58.2@90.94,54.864 91.44,54.364 91.44,54.229 v1(91.846,53.823) ; v1(91.114,10.973) 91.948,10.973 92.667,10.973 R40.2@93.48,10.16 ; v1(91.338,33.706) 91.669,34.036 92.151,34.036 R49.2@93.48,34.036 ; R38.2@91.44,8.644 92.432,8.644 92.892,9.104 v1(92.892,9.652) ; R43.2@91.448,17.272 91.448,17.89 91.846,18.289 v1(91.846,18.724) ; R53.2@91.448,42.672 91.448,42.054 91.846,41.655 v1(91.846,41.626) ; R37.2@91.948,11.184 92.66,11.184 92.871,10.973 v1(93.4,10.973) ; v1(92.024,48.362) 92.024,48.158 92.227,47.955 92.561,47.955 92.764,47.752 R55.2@93.48,47.752 ; v1(92.024,51.511) 92.024,51.308 R57.2@93.48,51.308 ; v1(92.028,59.842) 92.205,59.842 93.12,58.928 R59.2@93.48,58.928 ; v1(92.028,61.163) 92.307,61.163 93.018,60.452 R60.2@93.48,60.452 ; v1(92.431,21.133) 92.1,21.133 92.266,21.298 92.304,21.336 92.431,21.336 R44.2@93.48,21.336 ; v1(92.431,22.454) 92.024,22.454 92.024,22.352 92.431,22.352 R45.2@93.48,22.352 ; v1(92.431,26.416) R47.2@93.48,26.416 ; v1(92.434,40.437) 92.597,40.437 92.597,39.639 93.12,39.116 R52.2@93.48,39.116 ; v1(92.456,46.634) 92.456,46.431 92.659,46.228 R54.2@93.48,46.228 ; R41.2@93.48,12.192 92.235,13.437 ; R42.2@93.48,13.716 93.201,13.437 92.235,13.437 ; R46.2@93.48,24.892 93.48,23.9 93.935,23.444 v1(94.894,23.444) ; R51.2@93.48,37.592 94.928,36.144 v1(95.301,36.144) ; R56.2@93.48,50.292 94.488,49.284 v1(94.488,49.246) ; R61.2@93.48,62.992 93.48,62 93.94,61.54 v1(94.488,61.54) ; R39.2@94.48,8.636 95.301,9.457 v1(95.301,9.682) ; 88.265,15.621 88.265,14.021 88.849,13.437 92.235,13.437
  other v1: 95.453,30.734 78.892,41.808
5V: C6.1 IC2.4 IC2.5 IC2.16 JP2.4 | length 19.9
  Top Layer w0.2: JP2.4@3.048,11.176 3.048,10.363 5.207,8.204 8.23,8.204 8.23,8.21 IC2.4@8.636,8.21 IC2.5@8.636,7.56 IC2.16@15.036,7.56 ; v1(5.436,12.954) 6.604,14.122 C6.1@6.604,14.922
  Bottom Layer w0.2: JP2.4@3.048,11.176 4.826,12.954 v1(5.436,12.954)
AD0: JP8.2 R61.1 U1.61 | length 35.9
  Top Layer w0.2: U1.61@87.594,34.858 88.935,34.858 v1(89.84,35.763) ; v1(91.211,46.99) 91.211,51.206 91.364,51.359 91.364,52.019 92.507,53.162 92.507,53.594 93.396,54.483 93.396,58.522 94.285,59.411 94.285,60.249 JP8.2@97.028,62.992
  Bottom Layer w0.2: v1(89.84,35.763) 89.179,36.424 89.179,41.504 89.713,42.037 89.713,44.348 91.211,45.847 v1(91.211,46.99) ; R61.1@94.48,62.992 JP8.2@97.028,62.992
AD1: JP8.3 R60.1 U1.62 | length 41
  Top Layer w0.2: U1.62@87.594,35.358 88.85,35.358 88.9,35.408 88.9,39.294 89.408,39.802 91.034,39.802 91.034,44.583 90.634,44.983 89.764,44.983 88.494,46.253 88.494,47.346 88.798,47.65 89.814,47.65 90.297,47.168 90.297,46.533 90.856,45.974 92.888,45.974 93.116,46.203 93.116,51.283 94.691,52.857 94.691,58.115 JP8.3@97.028,60.452
  Bottom Layer w0.2: R60.1@94.48,60.452 JP8.3@97.028,60.452
AUD_IN: C17.1 JP3.12 R14.1 U3.8 U7.60 | length 89.9
  Top Layer w0.2: v1(14.63,55.524) 17.944,58.838 U3.8@17.944,59.084 17.944,61.138 17.131,61.951 v1(17.12,61.951) ; v1(20.65,57.074) 20.65,56.066 C17.1@20.836,55.88 20.836,55.474 20.828,55.466 20.828,54.864 R14.1@20.836,54.864 ; v1(35.662,39.954) 35.916,40.208 38.024,40.208 JP3.12@44.45,46.634 ; U7.60@41.47,49.058 41.47,49.741 41.453,49.759 41.453,51.054 41.859,51.46 43.612,51.46 44.552,50.521 JP3.12@44.552,46.736 ; JP3.12@44.45,46.736 JP3.12@44.45,46.634 ; JP3.12@44.45,46.609 JP3.12@44.45,46.634 ; JP3.12@44.45,46.609 44.45,46.279 44.12,46.279 JP3.12@44.45,46.609 ; JP3.12@44.45,46.609 44.514,46.672 44.552,46.711 JP3.12@44.552,46.736 ; JP3.12@44.45,46.634 44.501,46.685 JP3.12@44.552,46.736
  Bottom Layer w0.2: v1(14.63,55.524) 14.63,49.098 15.037,48.692 15.773,48.692 18.974,45.491 31.877,45.491 35.433,41.935 35.433,40.183 v1(35.662,39.954) ; v1(17.12,61.951) 17.704,62.535 17.704,62.789 18.237,63.322 18.491,63.322 21.158,65.989 21.158,66.878 21.173,66.893 21.173,68.341 21.895,69.063 23.368,69.063 24.359,68.072 24.359,66.192 21.539,63.373 21.539,57.963 v1(20.65,57.074)
AUD_OUT: C13.1 C28.2 JP3.11 R24.2 R25.2 R26.2 U7.59 | length 61.3
  Top Layer w0.2: C13.1@19.304,53.856 19.304,53.17 ; v1(19.964,48.108) 19.304,48.768 19.304,53.17 ; v1(19.99,53.162) 19.99,53.17 19.304,53.17 ; v1(23.266,66.065) 23.266,64.448 23.787,63.927 23.876,63.838 23.876,63.711 23.884,63.703 ; C28.2@23.876,64.016 23.876,64.033 24.189,64.033 24.206,64.016 ; R24.2@23.884,60.96 23.876,60.968 23.876,62.476 R26.2@23.884,62.484 23.884,63.703 ; R25.2@24.892,64.016 24.206,64.016 ; v1(40.691,51.638) 40.97,51.359 U7.59@40.97,49.058 ; 23.884,63.703 23.884,64.016 24.206,64.016
  Bottom Layer w0.2: v1(19.964,48.108) 19.964,47.346 20.904,46.406 27.947,46.406 29.827,48.285 33.553,48.285 36.906,51.638 v1(40.691,51.638) 40.691,49.784 41.834,48.641 42.875,48.641 43.129,48.387 43.129,47.6 43.18,47.549 JP3.11@43.18,46.736 ; v1(19.99,53.162) 19.99,57.734 20.879,58.623 20.879,63.678 v1(23.266,66.065)
AUD_REF: C7.1 R1.1 R2.2 U3.3 U3.5 U3.10 U3.12 | length 28
  Top Layer w0.2: C7.1@11.176,70.93 11.633,70.93 11.633,70.104 11.862,69.875 14.003,69.875 R2.2@14.224,70.096 14.232,70.104 15.232,70.104 R1.1@15.24,70.096 15.756,70.096 16.078,69.774 16.078,64.414 17.348,63.144 18.364,63.144 18.756,63.536 ; U3.10@19.244,59.084 19.244,59.792 19.228,59.792 19.228,60.833 19.507,61.112 ; U3.12@20.544,59.084 20.544,59.766 20.549,59.771 20.549,60.884 20.32,61.112 19.507,61.112 ; U3.3@20.544,65.024 20.544,65.994 20.32,66.218 19.507,66.218 19.244,65.955 U3.5@19.244,65.024 19.244,64.024 18.756,63.536 ; 18.756,63.536 18.756,61.432 19.075,61.112 19.507,61.112
DC_SOURCE: C1.2 IC1.1 IC1.8 J1.1 JP2.2 | length 71.4
  Top Layer w0.2: JP2.2@3.048,6.096 6.071,3.073 v1(11.836,3.073) ; v1(12.319,14.63) v1@15.088,14.63 ; IC1.1@15.24,15.748 15.24,14.656 v1(15.088,14.503) v1@15.088,14.63 ; IC1.8@16.24,20.628 16.24,21.488 14.021,21.488 13.284,20.752 5.41,20.752 5.182,20.523 5.182,17.602 6.096,16.688 14.986,16.688 15.088,16.586 15.088,15.748 v1@15.088,14.63 ; C1.2@17.78,8.318 18.567,7.531 ; v1(19.355,10.008) 19.355,8.318 18.567,7.531 ; J1.1@24.336,6.636 19.462,6.636 18.567,7.531
  Bottom Layer w0.2: v1(11.836,3.073) 12.319,3.556 v1(12.319,14.63) ; v1(15.088,14.503) 15.088,11.582 16.662,10.008 v1(19.355,10.008)
DF_CS: JP6.4 U5.17 U5A.11 U7.20 | length 76.9
  Top Layer w0.2: U7.20@41.97,61.058 41.97,61.773 42.173,61.976 43.129,61.976 44.552,63.398 44.958,63.398 JP6.4@44.958,64.008 ; v1(44.323,66.777) 45.136,65.964 50.419,65.964 v1(51.054,66.599) ; v1(44.9,21.336) 44.988,21.248 U5A.11@46.228,21.248 ; v1@48.55,21.336 48.55,21.626 48.64,21.716 50.597,21.716 50.8,21.513 50.8,21.285 v1@51.333,20.752 ; v1(53.365,41.148) 53.365,38.583 54.204,37.744 54.204,32.944 52.476,31.217 52.476,26.264 53.289,25.451 53.289,20.955 53.492,20.752 v1(53.899,20.752)
  Bottom Layer w0.2: v1(44.323,66.777) 44.323,64.643 JP6.4@44.958,64.008 ; v1(44.9,21.336) v1@48.55,21.336 ; v1(51.054,66.599) 52.832,66.599 54.051,65.38 54.051,63.322 53.365,62.636 v1(53.365,41.148) ; v1@51.333,20.752 v1(53.899,20.752)
  other v1: 51.1,20.752 48.51,21.336
DF_RDY: JP4.12 U5.5 U5A.1 U7.12 | length 71.6
  Top Layer w0.2: U7.12@45.72,56.808 47.879,56.808 48.424,57.353 49.276,57.353 50.444,58.522 50.444,59.373 51.777,60.706 JP4.12@52.324,60.706 53.188,59.842 53.188,57.683 53.645,57.226 56.972,57.226 58.166,56.032 58.166,47.574 57.633,47.041 57.633,37.948 57.506,37.821 57.506,30.226 56.49,29.21 54.813,29.21 v1(53.797,28.194) ; U5A.1@46.228,15.748 v1(47.5,15.748) ; v1(47.244,14.224) 48.744,14.2 48.768,14.224 48.768,15.69 48.794,15.716 50.8,15.716 51.283,16.199 v1(51.283,16.713)
  Bottom Layer w0.2: v1(47.244,14.224) 47.5,14.48 v1(47.5,15.748) ; v1(51.283,16.713) 52.857,16.713 54.559,18.415 54.559,21.031 53.797,21.793 v1(53.797,28.194)
DF_RESET: JP6.7 U5.6 U5A.2 U7.23 | length 77
  Top Layer w0.2: v1(40.462,59.893) v1@40.47,59.901 ; U7.23@40.47,61.058 40.47,59.817 39.141,58.488 39.141,54.788 34.595,50.241 31.598,50.241 28.651,47.295 27.711,47.295 26.518,46.101 26.518,44.475 26.822,44.171 27.203,44.171 27.28,44.094 27.28,34.976 34.798,27.457 40.691,27.457 43.917,24.232 43.917,18.136 45.212,16.84 45.212,15.24 45.72,14.732 46.736,15.24 48.26,14.732 48.26,15.748 48.728,16.216 U5.6@49.784,16.216 ; 45.214,16.258 45.254,16.298 U5A.2@46.228,16.298
  Bottom Layer w0.2: v1(40.462,59.893) 40.742,60.173 40.742,63.602 JP6.7@41.148,64.008
GND: BT1.2 C1.1 C2.1 C3.2 C6.2 C7.2 C10.1 C11.1 C12.2 C15.2 C18.1 C19.1 C20.1 C21.1 C22.1 C23.1 C24.2 C25.2 C26.1 C27.1 C28.1 C29.1 C30.1 C31.1 C33.1 C34.1 C35.1 C36.1 C37.1 C39.1 C40.1 C41.1 C42.1 C43.1 C44.1 C45.1 C46.1 C47.1 C48.2 C49.1 C50.1 C51.1 C52.1 C54.1 C56.1 C57.2 IC1.2 IC1.3 IC1.4 IC1.6 IC1.7 IC1.10 IC2.1 IC2.2 IC2.9 IC2.10 IC2.11 IC2.12 IC2.18 IC2.19 IC2.20 J1.3 J2.5 J3.5 JP1.9 JP2.1 JP3.14 JP3.15 JP7.1 JP7.2 JP8.25 L3.1 MK1.1 P1.2@90.942,70.622 Q1.3 R2.1 R17.1 R18.1 R20.2 R21.2 R22.2 R23.2 R25.1 R30.1 R31.1 S1.1@59.726,58.001 S2.1@59.726,44.285 S3.1@59.726,30.061 U1.3 U1.7 U1.8 U1.9 U1.16 U1.17 U1.22 U1.23 U1.24 U1.25 U1.32 U1.41 U1.49 U1.64 U2.15 U3.11 U4.8 U5.12 U5A.7 U6.8 U7.62 U7.63 | length 191.6
  Top Layer w0.2: C6.2@6.604,19.622 v1(8.181,19.622) ; v1(6.619,10.16) IC2.1@8.636,10.16 ; IC2.10@8.636,4.31 v1(10.653,4.31) ; IC2.9@8.636,4.96 v1(9.688,4.96) ; IC2.2@8.636,9.51 9.83,9.51 v1(10.643,8.697) ; v1(9.144,66.548) C7.2@11.176,66.23 ; C3.2@9.652,19.622 10.973,19.622 11.227,19.368 v1(11.227,18.403) ; C7.2@11.267,66.139 R2.1@14.224,69.096 ; v1(12.014,19.837) 15.037,19.837 15.24,20.041 IC1.10@15.24,20.628 ; v1(13.019,4.96) IC2.12@15.036,4.96 ; v1(13.019,10.16) IC2.20@15.036,10.16 ; v1(13.259,8.556) 13.259,9.05 13.718,9.51 IC2.19@15.036,9.51 ; v1(13.984,8.86) IC2.18@15.036,8.86 ; IC2.11@15.036,4.31 16.637,4.31 v1(17.043,3.904) ; v1(15.291,50.685) 15.291,50.025 15.85,49.466 C15.2@17.272,49.466 ; v1(15.74,13.756) IC1.2@15.74,15.748 ; v1(16.203,13.018) C1.1@17.78,13.018 ; IC1.3@16.24,15.748 v1(16.24,16.775) ; v1(16.74,14.721) IC1.4@16.74,15.748 ; v1(16.74,19.601) IC1.7@16.74,20.628 ; IC1.6@17.24,20.628 v1(17.24,22.62) ; U3.11@19.894,59.084 v1(19.894,60.451) ; C12.2@20.32,69.588 C11.1@19.304,69.588 19.304,69.596 20.078,70.37 20.586,70.37 20.828,70.612 20.828,71.99 23.514,71.99 v1(24.384,71.12) ; C10.1@21.836,53.34 22.2,52.976 22.2,52.756 v1(23.063,51.892) ; C28.1@23.876,65.016 23.876,65.557 24.79,66.472 v1(25.298,66.472) ; R25.1@24.892,65.016 25.959,66.083 25.959,67.285 v1(25.806,67.285) ; v1(25.718,15.695) C2.1@25.718,17.272 ; v1(42.47,47.981) U7.62@42.47,49.058 ; U7.63@42.97,49.058 v1(42.97,50.135) ; v1(44.9,19.304) 45.156,19.048 U5A.7@46.228,19.048 ; v1(48.607,19.216) U5.12@49.784,19.216 ; C57.2@48.76,41.148 49.581,40.327 49.581,40.107 v1(49.174,39.7) ; C25.2@48.76,42.164 48.76,42.571 49.581,43.392 v1(49.581,43.616) ; v1(50.216,41.808) 50.216,42.227 50.61,42.621 C24.2@50.61,44.196 ; C26.1@56.388,48.776 57.273,48.776 v1(57.506,48.543) ; C27.1@56.388,67.556 56.388,67.894 56.693,68.199 v1(57.099,68.199) ; C19.1@57.404,13.216 57.404,12.449 57.596,12.257 57.687,12.167 v1(57.506,12.167) ; C18.1@57.404,25.392 57.904,25.392 58.318,25.806 v1(58.318,26.441) ; v1(59.726,27.996) S3.1@59.726,30.061 ; v1(59.726,43.033) S2.1@59.726,44.285 ; v1(59.726,56.749) S1.1@59.726,58.001 ; C30.1@61.976,54.364 61.976,53.953 62.789,53.14 v1(62.789,52.506) ; v1(61.976,67.64) 62.484,68.148 C29.1@62.484,69.096 ; C31.1@62.992,40.648 63.458,40.648 64.161,41.351 v1(64.851,41.351) ; v1(63.398,20.599) 63.398,20.396 63.602,20.193 U6.8@64.516,20.193 ; R17.1@66.548,8.12 66.548,8.836 66.751,9.039 66.751,9.347 66.98,9.576 v1(67.158,9.576) ; C23.1@70.612,8.12 71.391,8.899 71.526,9.034 v1(71.526,8.763) ; C51.1@71.628,23.376 71.628,22.762 72.034,22.355 v1(72.034,21.924) ; v1(72.136,36.043) C50.1@72.136,37.092 ; C49.1@72.136,42.664 72.136,43.657 72.596,44.116 v1(73.355,44.116) ; C48.2@72.136,51.808 72.136,52.801 72.596,53.26 v1(73.355,53.26) ; v1(72.314,4.775) 72.314,4.597 72.542,4.369 73.363,4.369 C54.1@74.168,3.564 ; v1(72.746,32.952) 73.152,33.358 U1.23@75.594,33.358 ; v1(73.943,42.672) C45.1@76.716,42.672 ; v1(74.168,10.973) 74.575,11.38 U2.15@74.575,12.427 ; R31.1@74.176,39.624 74.676,39.124 v1(74.676,38.172) ; v1(74.517,32.358) U1.25@75.594,32.358 ; v1(74.517,36.358) U1.17@75.594,36.358 ; C52.1@74.668,14.732 75.532,15.596 75.667,15.596 v1(75.971,15.9) 76.124,16.053 v1@76.124,16.154 ; v1(74.955,51.918) 76.106,51.918 C39.1@77.224,50.8 ; U1.32@75.594,28.858 77.651,28.858 78.054,29.261 v1(78.449,29.261) ; U1.24@75.594,32.858 v1(78.043,32.858) ; U1.22@75.594,33.858 v1(76.671,33.858) ; v1(76.585,53.238) 76.31,53.238 76.447,53.101 C37.1@77.224,52.324 ; C47.1@76.716,41.148 76.716,39.971 77.318,39.369 77.318,38.786 v1(76.911,38.379) ; C46.1@76.716,44.196 76.716,44.713 77.318,45.314 v1(77.318,45.648) ; C56.1@77.216,3.564 77.216,2.797 77.318,2.696 v1(77.318,2.112) ; C36.1@77.224,54.356 77.224,55.127 77.318,55.22 v1(77.318,55.808) ; U1.16@77.844,38.608 v1(77.844,39.685) ; C43.1@80.272,24.384 79.832,23.944 79.832,22.606 80.005,22.433 80.874,22.433 81.249,22.433 81.28,22.402 81.28,22.073 81.128,21.92 80.874,21.92 v1(80.874,22.017) ; v1(81.125,36.576) 81.328,36.576 82.344,37.592 U1.7@82.344,38.608 ; v1@81.344,36.795 U1.9@81.344,38.608 ; v1(81.788,22.327) 81.796,22.335 C42.1@81.796,23.368 ; U1.41@81.844,26.608 81.844,29.088 82.093,29.337 v1(82.093,29.743) ; 81.844,37.092 U1.8@81.844,38.608 ; v1(82.906,43.536) 82.906,42.469 83.519,41.855 83.726,41.648 ; C44.1@83.312,41.648 83.726,41.648 ; v1(83.668,30.683) 83.668,29.661 85.121,28.208 86.061,28.208 86.711,28.858 U1.49@87.594,28.858 ; U1.3@84.344,38.608 84.344,36.982 v1(84.75,36.576) ; v1(86.517,36.358) U1.64@87.594,36.358 ; L3.1@86.852,48.768 87.554,48.768 87.554,49.301 v1(87.833,49.581) ; v1(87.401,41.148) 86.901,41.648 86.784,41.648 C41.1@85.852,41.648 C40.1@84.836,41.648 83.726,41.648 ; v1(89.713,33.503) 89.924,33.714 C33.1@89.924,34.544 ; C34.1@89.916,28.964 89.916,28.143 90.195,27.864 90.195,27.584 90.119,27.508 v1(90.119,27.102) ; C35.1@90.924,36.576 91.745,35.755 v1(91.745,35.124) ; R30.1@90.924,37.592 90.924,38.638 90.924,38.989 90.932,38.989 v1(90.932,38.638) ; P1.2@90.942,70.622 v1(90.942,71.949)
  Bottom Layer w0.2: C21.1@61.468,43.188 61.883,43.188 62.688,43.993 v1(62.92,43.993) ; C22.1@61.968,31.496 62.103,31.361 62.103,30.73 v1(62.789,30.044) ; C20.1@63.468,41.656 v1(63.468,42.933) ; R18.1@64.516,30.996 64.516,30.636 65.43,29.721 v1(65.43,29.544) ; U4.8@64.516,34.163 65.43,34.163 65.684,34.417 65.684,34.874 v1(65.786,34.976) ; v1(82.939,7.747) R21.2@83.82,8.628 ; R23.2@83.82,20.312 84.861,21.353 v1(84.861,21.539) ; v1(90.119,21.768) 90.221,21.768 90.424,21.565 R20.2@90.424,20.312 ; R22.2@91.44,6.088 91.44,6.731 92.253,7.544 v1(92.659,7.544)
IR_CS: JP6.5 U6.4 U7.21 | length 101.3
  Top Layer w0.2: 41.47,59.174 U7.21@41.47,61.058 ; v1(41.478,59.656) 39.548,57.725 39.548,53.95 34.62,49.022 31.039,49.022 28.702,46.685 28.702,39.903 30.531,38.075 30.531,34.341 32.004,32.868 36.601,32.868 v1(43.688,25.4) ; U6.4@64.516,17.653 66.116,17.653 66.142,17.678 68.148,17.678 69.367,16.459 v1(69.367,15.723)
  Bottom Layer w0.2: v1(41.478,59.656) 43.688,61.865 JP6.5@43.688,64.008 ; v1(43.688,25.4) 43.915,14.886 44.348,14.707 44.729,14.707 45.923,13.513 57.379,13.513 59.258,15.392 61.138,15.392 61.366,15.164 68.809,15.164 v1(69.367,15.723)
IR_IRQ: JP4.13 U6.6 U7.13 | length 61.2
  Top Layer w0.2: U7.13@45.72,57.308 47.65,57.308 51.861,61.519 52.324,61.519 52.781,61.519 ; JP4.13@52.324,61.976 52.781,61.519 ; v1(62.027,19.787) 62.89,18.923 U6.6@64.516,18.923 ; v1(63.627,26.111) 61.874,27.864 61.874,33.376 58.369,36.881 58.369,46.685 58.572,46.888 58.572,56.192 57.132,57.633 54,57.633 53.594,58.039 53.594,60.706 52.781,61.519
  Bottom Layer w0.2: v1(62.027,19.787) 62.433,20.193 62.433,24.917 v1(63.627,26.111)
IR_SHDN: JP6.8 U6.7 U7.24 | length 69.6
  Top Layer w0.2: JP6.8@39.878,64.008 39.878,63.5 39.97,63.408 U7.24@39.97,61.058 ; v1(44.501,53.95) 44.501,51.206 v1(46.33,49.378) ; v1(51.816,42.926) 52.07,42.672 52.07,38.405 53.416,37.059 53.416,34.544 52.07,33.198 52.07,23.317 52.832,22.555 52.832,20.498 53.238,20.091 55.575,20.091 56.337,20.853 62.103,20.853 63.398,19.558 U6.7@64.516,19.558
  Bottom Layer w0.2: JP6.8@39.878,64.008 39.802,63.932 39.802,59.538 40.64,58.699 43.891,58.699 44.501,58.09 v1(44.501,53.95) ; v1(46.33,49.378) 49.53,49.378 50.749,48.158 50.749,43.79 51.613,42.926 v1(51.816,42.926)
LCD_CS: JP6.6 U4.15 U7.22 | length 79.5
  Top Layer w0.2: U7.22@40.97,61.058 40.97,62.56 JP6.6@42.418,64.008 41.478,64.948 31.445,64.948 31.445,67.666 32.207,68.428 46.812,68.428 48.108,69.723 57.937,69.723 58.572,69.088 58.572,66.396 v1(58.242,66.065)
  Bottom Layer w0.2: v1(58.242,66.065) 58.242,50.343 60.02,48.565 60.02,44.958 58.75,43.688 58.75,40.132 59.461,39.421 59.461,38.202 59.233,37.973 U4.15@58.496,37.973
MISO: JP7.5 R37.1 U1.51 | length 35
  Top Layer w0.2: v1(80.264,13.97) 85.598,13.97 86.309,13.259 88.595,13.259 89.002,12.852 89.002,12.192 JP7.5@89.408,12.192 ; v1(86.233,21.692) 88.519,23.978 88.519,29.858 U1.51@87.594,29.858
  Bottom Layer w0.2: v1(80.264,13.97) 79.985,14.249 79.985,16.332 80.467,16.815 81.432,16.815 82.906,18.288 84.938,18.288 86.233,19.583 v1(86.233,21.692) ; JP7.5@89.408,12.192 90.162,12.192 90.17,12.184 R37.1@91.948,12.184
MOSI: JP7.4 R32.1 U1.34 | length 26.5
  Top Layer w0.2: U1.34@78.344,26.608 78.344,25.872 78.689,25.527 v1(78.689,24.155)
  Bottom Layer w0.2: v1(78.689,24.155) 78.689,24.028 79.047,23.671 79.047,21.084 78.689,20.726 78.689,14.98 78.283,14.573 78.283,10.566 79.197,9.652 83.812,9.652 R32.1@84.828,10.668 85.852,10.668 JP7.4@86.868,9.652
MOTOR: JP5.4 Q1.2 U7.36 | length 61.1
  Top Layer w0.2: Q1.2@12.7,23.368 20.218,23.368 21.438,24.587 21.438,47.879 24.13,50.571 v1(24.13,50.775) ; JP5.4@27.432,63.754 28.245,62.941 28.245,61.087 32.024,57.308 U7.36@33.72,57.308
  Bottom Layer w0.2: v1(24.13,50.775) 24.13,60.325 27.102,63.297 27.432,63.297 JP5.4@27.432,63.754
NetB1_2: B1.2 Q1.1 | length 4.8
  Top Layer w0.2: B1.2@8.344,23.636 9.346,24.638 Q1.1@12.7,24.638
NetBT1_1: BT1.1 J1.2 | length 34.6
  Top Layer w0.2: BT1.1@3.048,20.574 4.369,19.253 4.369,12.294 5.283,11.379 19.837,11.379 21.581,9.636 J1.2@29.036,9.636
NetC4_1: C4.1 IC2.6 | length 17.2
  Top Layer w0.2: C4.1@6.096,9.112 5.69,9.112 5.69,10.211 3.658,12.243 2.438,12.243 1.981,11.786 1.981,7.823 2.438,7.366 6.909,7.366 7.365,6.91 IC2.6@8.636,6.91
NetC4_2: C4.2 IC2.8 | length 2.7
  Top Layer w0.2: C4.2@6.096,5.112 7.325,5.112 7.823,5.61 IC2.8@8.636,5.61
NetC5_1: C5.1 IC2.13 | length 5.1
  Top Layer w0.2: IC2.13@15.036,5.61 16.662,5.61 17.78,4.492 C5.1@17.78,2.572
NetC5_2: C5.2 IC2.15 | length 2.9
  Top Layer w0.2: IC2.15@15.036,6.91 15.893,6.91 16.231,6.572 C5.2@17.78,6.572
NetC8_1: C8.1 R5.2 U3.13 | length 9.7
  Top Layer w0.2: U3.13@21.194,59.084 21.194,57.76 22.027,56.927 v1@22.083,56.871 ; v1(22.377,56.871) 23.368,55.88 C8.1@23.376,55.88
  Bottom Layer w0.2: R5.2@20.836,51.816 22.377,53.357 v1(22.377,56.871)
NetC8_2: C8.2 R4.2 R6.1 U3.14 | length 20.1
  Top Layer w0.2: v1(19.406,61.773) 20.904,61.773 21.844,60.833 U3.14@21.844,59.084 21.844,57.675 21.861,57.658 22.598,57.658 C8.2@24.376,55.88 R6.1@24.376,54.864
  Bottom Layer w0.2: R4.2@18.804,52.324 19.228,52.748 19.228,61.773 v1(19.406,61.773)
NetC9_1: C9.1 R8.2 U3.2 | length 21.2
  Top Layer w0.2: U3.2@21.194,65.024 21.194,63.195 21.423,62.967 21.615,62.967 22.479,63.83 ; C9.1@21.336,68.588 21.336,68.123 21.539,67.92 21.793,67.92 22.479,67.234 22.479,63.83 ; R8.2@24.376,53.34 24.638,53.34 25.349,54.051 25.349,58.522 23.139,60.731 23.139,63.17 22.479,63.83
NetC9_2: C9.2 R7.2 R9.1 U3.1 | length 14.1
  Top Layer w0.2: R7.2@18.288,69.588 17.729,69.029 17.729,68.021 18.288,68.021 18.593,67.716 18.593,66.878 18.694,66.777 v1(21.819,66.777) ; v1@21.819,66.497 21.844,66.472 U3.1@21.844,65.024 ; R9.1@21.828,71.12 21.828,70.12 21.844,70.104 21.336,70.104 C9.2@21.336,69.588 22.25,68.674 v1(22.25,68.402)
  Bottom Layer w0.2: v1@21.819,66.497 v1(21.819,66.777) 22.25,67.208 v1(22.25,68.402)
NetC10_2: C10.2 R3.2 R4.1 R5.1 | length 11.3
  Top Layer w0.2: R3.2@19.304,57.396 19.863,56.837 19.863,54.313 C10.2@20.836,53.34 21.742,52.434 v1(21.742,50.97)
  Bottom Layer w0.2: R4.1@19.804,52.324 19.804,51.773 20.32,51.257 21.742,51.257 v1(21.742,50.97) 21.836,51.063 R5.1@21.836,51.816
NetC11_2: C11.2 R6.2 R7.1 R8.1 | length 27.7
  Top Layer w0.2: R7.1@18.288,68.588 18.288,68.605 18.601,68.605 18.618,68.588 C11.2@19.304,68.588 v1(19.304,67.666) ; v1(20.218,62.433) 21.539,62.433 22.555,61.417 22.555,59.055 24.943,56.667 24.943,54.305 24.341,54.305 24.138,54.102 ; R8.1@23.376,53.34 24.138,54.102 ; R6.2@23.376,54.864 24.138,54.102
  Bottom Layer w0.2: v1(19.304,67.666) 19.304,65.269 16.383,62.348 16.383,61.57 16.84,61.112 17.78,61.112 19.101,62.433 v1(20.218,62.433)
NetC13_2: C13.2 R3.1 | length 1.5
  Top Layer w0.2: C13.2@19.304,54.856 R3.1@19.304,56.396
NetC14_1: C14.1 R10.2 U3.7 | length 31.8
  Top Layer w0.2: C14.1@6.604,56.198 4.711,56.198 3.81,57.099 3.81,59.055 4.369,59.614 v1@15.037,59.614 ; v1@17.323,67.361 17.323,70.147 R10.2@17.788,70.612 ; v1(17.526,67.361) 17.944,66.943 17.944,66.181 U3.7@17.944,65.024
  Bottom Layer w0.2: v1@15.037,59.614 15.037,65.786 16.612,67.361 v1(17.526,67.361)
  other v1: 15.24,59.436
NetC14_2: C14.2 J2.4 | length 4.3
  Top Layer w0.2: J2.4@3.99,49.244 3.99,50.597 4.891,51.498 C14.2@6.604,51.498
NetC15_1: C15.1 R11.2 R12.2 | length 6.1
  Top Layer w0.2: R11.2@11.684,52.824 R12.2@12.7,52.824 14.042,54.166 C15.1@17.272,54.166
NetC16_1: C16.1 R13.2 | length 1.8
  Top Layer w0.2: C16.1@10.668,52.824 10.389,53.103 10.389,54.085 R13.2@10.668,54.364
NetC16_2: C16.2 J2.1 R11.1 | length 4.1
  Top Layer w0.2: J2.1@10.59,49.244 11.684,50.338 R11.1@11.684,51.816 ; C16.2@10.668,51.824 10.676,51.816 R11.1@11.684,51.816 ; R11.1@11.684,51.824 R11.1@11.684,51.816
NetC17_2: C17.2 R13.1 R14.2 U3.9 | length 32.8
  Top Layer w0.2: 10.416,55.372 13.716,55.372 14.224,54.864 15.24,54.864 15.748,55.372 18.694,55.372 ; R13.1@10.668,55.364 R13.1@10.668,55.372 ; U3.9@18.694,58.984 18.694,48.158 19.507,47.346 20.218,47.346 20.625,47.752 20.625,48.489 23.724,51.587 23.724,52.222 23.165,52.781 22.809,52.781 22.809,54.331 22.276,54.864 ; R14.2@21.836,54.864 22.276,54.864 ; C17.2@21.836,55.88 22.276,55.44 22.276,54.864
NetC18_2: C18.2 U6.9 Y1.1 | length 10.2
  Top Layer w0.2: Y1.1@54.356,24.062 54.356,24.079 57.404,24.079 ; C18.2@57.404,24.392 57.404,24.079 ; v1(58.369,24.079) 57.404,24.079 ; U6.9@58.496,20.193 v1(59.868,20.193)
  Bottom Layer w0.2: v1(58.369,24.079) 59.868,22.581 v1(59.868,20.193)
NetC19_2: C19.2 U6.10 Y1.2 | length 12.2
  Top Layer w0.2: C19.2@57.404,14.216 54.356,14.216 Y1.2@54.356,15.562 54.356,19.05 54.864,19.558 U6.10@58.496,19.558
NetC22_2: C22.2 U4.9 | length 11.1
  Top Layer w0.2: v1(58.649,28.931) 58.649,32.715 59.766,33.833 v1(59.766,34.163)
  Bottom Layer w0.2: U4.9@58.496,34.163 v1(59.766,34.163) ; v1(58.649,28.931) 59.741,28.931 60.968,30.158 C22.2@60.968,31.496
NetC23_2: C23.2 D1.2 R15.1 | length 4.4
  Top Layer w0.2: D1.2@69.088,5.08 D1.2@69.596,5.588 ; R15.1@69.088,7.12 69.088,6.096 D1.2@69.596,5.588 ; C23.2@70.612,7.12 70.612,6.604 D1.2@69.596,5.588
NetC26_2: C26.2 JP4.8 U7.8 Y2.2 | length 16.5
  Top Layer w0.2: U7.8@45.72,54.808 51.506,54.808 JP4.8@52.324,55.626 52.857,55.093 56.388,55.093 Y2.2@56.388,53.662 C26.2@56.388,49.776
